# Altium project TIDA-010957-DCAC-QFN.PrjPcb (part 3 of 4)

## Sheet TIDA-010957-DCAC-Current-Sensing.SchDoc
size 431 x 279 mm; Date: Not shown in title block; ApprovedBy: Not shown in title block; CheckedBy: Not shown in title block; Author: Not shown in title block; CompanyName: Not shown in title block; Engineer: Not shown in title block; Organization: Not shown in title block; Address1: Not shown in title block; Address2: Not shown in title block; Address3: Not shown in title block; Address4: Not shown in title block; DocumentNumber: 1; Revision: Use project parameter SCH_Rev; SheetNumber: 6; SheetTotal: 12; PageSetup: Record=PageOptions¦CenterHorizontal=True¦CenterVertical=True¦PrintScale=1.00¦XCorrection=1.00¦YCorrection=1.00¦PrintKind=0¦BorderSize=5000000¦LeftOffset=0¦BottomOffset=0¦Orientation=2¦PaperLength=1000¦PaperWidth=1000¦Scale=100¦PaperSource=15¦PrintQuality=600¦MediaType=1¦DitherType=10¦PaperKind=Letter¦PrintScaleMode=1
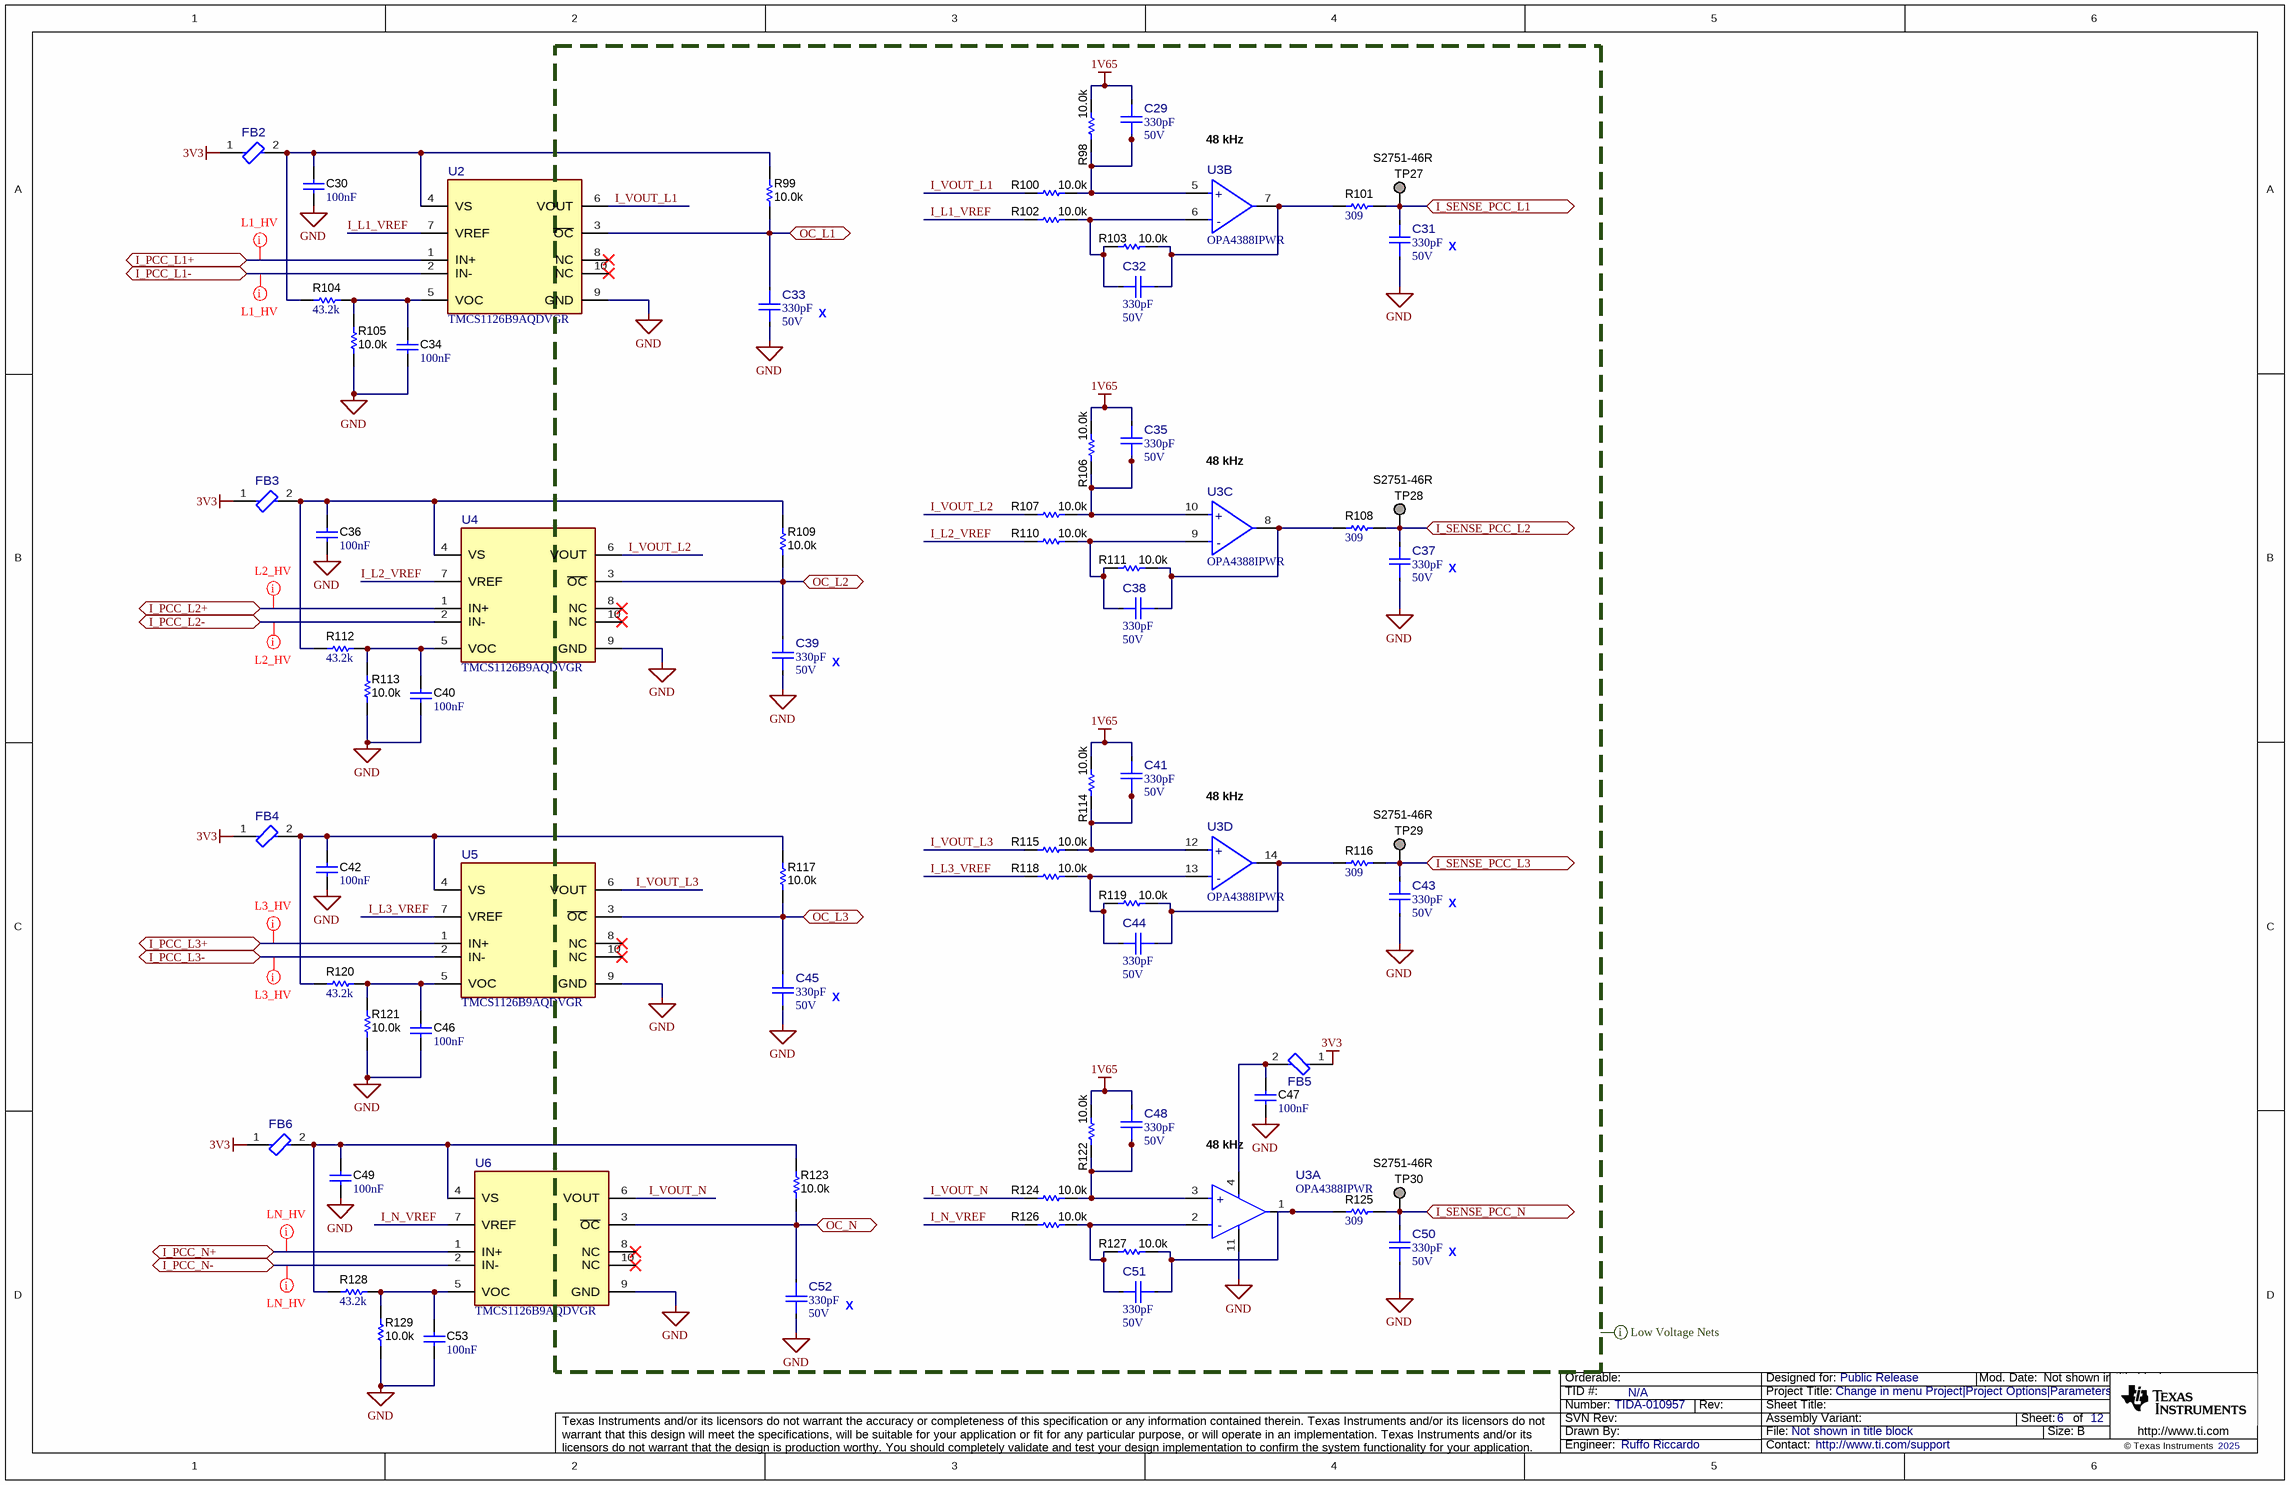
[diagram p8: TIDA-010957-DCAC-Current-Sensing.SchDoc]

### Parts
C29  ValueDisplayed: 330pF  VDC_V: 50V  [FP-CGA3E2C0G1H331J080AA_0603-MFG]  (hidden comment: CGA3E2C0G1H331J080AA)
C30  Cap_F: 100nF  [0603]  (hidden comment: 06033C104JAT2A)
C31  ValueDisplayed: 330pF  VDC_V: 50V  [FP-CGA3E2C0G1H331J080AA_0603-MFG]  (hidden comment: CGA3E2C0G1H331J080AA)
C32  ValueDisplayed: 330pF  VDC_V: 50V  [FP-CGA3E2C0G1H331J080AA_0603-MFG]  (hidden comment: CGA3E2C0G1H331J080AA)
C33  ValueDisplayed: 330pF  VDC_V: 50V  [FP-CGA3E2C0G1H331J080AA_0603-MFG]  (hidden comment: CGA3E2C0G1H331J080AA)
C34  Cap_F: 100nF  [0603]  (hidden comment: 06033C104JAT2A)
C35  ValueDisplayed: 330pF  VDC_V: 50V  [FP-CGA3E2C0G1H331J080AA_0603-MFG]  (hidden comment: CGA3E2C0G1H331J080AA)
C36  Cap_F: 100nF  [0603]  (hidden comment: 06033C104JAT2A)
C37  ValueDisplayed: 330pF  VDC_V: 50V  [FP-CGA3E2C0G1H331J080AA_0603-MFG]  (hidden comment: CGA3E2C0G1H331J080AA)
C38  ValueDisplayed: 330pF  VDC_V: 50V  [FP-CGA3E2C0G1H331J080AA_0603-MFG]  (hidden comment: CGA3E2C0G1H331J080AA)
C39  ValueDisplayed: 330pF  VDC_V: 50V  [FP-CGA3E2C0G1H331J080AA_0603-MFG]  (hidden comment: CGA3E2C0G1H331J080AA)
C40  Cap_F: 100nF  [0603]  (hidden comment: 06033C104JAT2A)
C41  ValueDisplayed: 330pF  VDC_V: 50V  [FP-CGA3E2C0G1H331J080AA_0603-MFG]  (hidden comment: CGA3E2C0G1H331J080AA)
C42  Cap_F: 100nF  [0603]  (hidden comment: 06033C104JAT2A)
C43  ValueDisplayed: 330pF  VDC_V: 50V  [FP-CGA3E2C0G1H331J080AA_0603-MFG]  (hidden comment: CGA3E2C0G1H331J080AA)
C44  ValueDisplayed: 330pF  VDC_V: 50V  [FP-CGA3E2C0G1H331J080AA_0603-MFG]  (hidden comment: CGA3E2C0G1H331J080AA)
C45  ValueDisplayed: 330pF  VDC_V: 50V  [FP-CGA3E2C0G1H331J080AA_0603-MFG]  (hidden comment: CGA3E2C0G1H331J080AA)
C46  Cap_F: 100nF  [0603]  (hidden comment: 06033C104JAT2A)
C47  Cap_F: 100nF  [0603]  (hidden comment: 06033C104JAT2A)
C48  ValueDisplayed: 330pF  VDC_V: 50V  [FP-CGA3E2C0G1H331J080AA_0603-MFG]  (hidden comment: CGA3E2C0G1H331J080AA)
C49  Cap_F: 100nF  [0603]  (hidden comment: 06033C104JAT2A)
C50  ValueDisplayed: 330pF  VDC_V: 50V  [FP-CGA3E2C0G1H331J080AA_0603-MFG]  (hidden comment: CGA3E2C0G1H331J080AA)
C51  ValueDisplayed: 330pF  VDC_V: 50V  [FP-CGA3E2C0G1H331J080AA_0603-MFG]  (hidden comment: CGA3E2C0G1H331J080AA)
C52  ValueDisplayed: 330pF  VDC_V: 50V  [FP-CGA3E2C0G1H331J080AA_0603-MFG]  (hidden comment: CGA3E2C0G1H331J080AA)
C53  Cap_F: 100nF  [0603]  (hidden comment: 06033C104JAT2A)
FB2  MH1608-601Y  [FP-MH1608-601Y_0603-MFG]  (value not drawn)
FB3  MH1608-601Y  [FP-MH1608-601Y_0603-MFG]  (value not drawn)
FB4  MH1608-601Y  [FP-MH1608-601Y_0603-MFG]  (value not drawn)
FB5  MH1608-601Y  [FP-MH1608-601Y_0603-MFG]  (value not drawn)
FB6  MH1608-601Y  [FP-MH1608-601Y_0603-MFG]  (value not drawn)
R98  ValueDisplayed: 10.0k  [0402L]  (hidden comment: MCS0402MD1002BE100)
R99  ValueDisplayed: 10.0k  [0603]  (hidden comment: CRCW060310K0FKEA)
R100  ValueDisplayed: 10.0k  [0402L]  (hidden comment: MCS0402MD1002BE100)
R101  ValueDisplayed: 309  [0402L]  (hidden comment: CRCW0402309RFKED)
R102  ValueDisplayed: 10.0k  [0402L]  (hidden comment: MCS0402MD1002BE100)
R103  ValueDisplayed: 10.0k  [0402L]  (hidden comment: MCS0402MD1002BE100)
R104  ValueDisplayed: 43.2k  [0603]  (hidden comment: RC0603FR-0743K2L)
R105  ValueDisplayed: 10.0k  [0603]  (hidden comment: CRCW060310K0FKEA)
R106  ValueDisplayed: 10.0k  [0402L]  (hidden comment: MCS0402MD1002BE100)
R107  ValueDisplayed: 10.0k  [0402L]  (hidden comment: MCS0402MD1002BE100)
R108  ValueDisplayed: 309  [0402L]  (hidden comment: CRCW0402309RFKED)
R109  ValueDisplayed: 10.0k  [0603]  (hidden comment: CRCW060310K0FKEA)
R110  ValueDisplayed: 10.0k  [0402L]  (hidden comment: MCS0402MD1002BE100)
R111  ValueDisplayed: 10.0k  [0402L]  (hidden comment: MCS0402MD1002BE100)
R112  ValueDisplayed: 43.2k  [0603]  (hidden comment: RC0603FR-0743K2L)
R113  ValueDisplayed: 10.0k  [0603]  (hidden comment: CRCW060310K0FKEA)
R114  ValueDisplayed: 10.0k  [0402L]  (hidden comment: MCS0402MD1002BE100)
R115  ValueDisplayed: 10.0k  [0402L]  (hidden comment: MCS0402MD1002BE100)
R116  ValueDisplayed: 309  [0402L]  (hidden comment: CRCW0402309RFKED)
R117  ValueDisplayed: 10.0k  [0603]  (hidden comment: CRCW060310K0FKEA)
R118  ValueDisplayed: 10.0k  [0402L]  (hidden comment: MCS0402MD1002BE100)
R119  ValueDisplayed: 10.0k  [0402L]  (hidden comment: MCS0402MD1002BE100)
R120  ValueDisplayed: 43.2k  [0603]  (hidden comment: RC0603FR-0743K2L)
R121  ValueDisplayed: 10.0k  [0603]  (hidden comment: CRCW060310K0FKEA)
R122  ValueDisplayed: 10.0k  [0402L]  (hidden comment: MCS0402MD1002BE100)
R123  ValueDisplayed: 10.0k  [0603]  (hidden comment: CRCW060310K0FKEA)
R124  ValueDisplayed: 10.0k  [0402L]  (hidden comment: MCS0402MD1002BE100)
R125  ValueDisplayed: 309  [0402L]  (hidden comment: CRCW0402309RFKED)
R126  ValueDisplayed: 10.0k  [0402L]  (hidden comment: MCS0402MD1002BE100)
R127  ValueDisplayed: 10.0k  [0402L]  (hidden comment: MCS0402MD1002BE100)
R128  ValueDisplayed: 43.2k  [0603]  (hidden comment: RC0603FR-0743K2L)
R129  ValueDisplayed: 10.0k  [0603]  (hidden comment: CRCW060310K0FKEA)
TP27  S2751-46R  [Harwin_S2751-46R]  (no BOM)
TP28  S2751-46R  [Harwin_S2751-46R]  (no BOM)
TP29  S2751-46R  [Harwin_S2751-46R]  (no BOM)
TP30  S2751-46R  [Harwin_S2751-46R]  (no BOM)
U2  TMCS1126B9AQDVGR  [DVG0010A-MFG]
U3  OPA4388IPWR  [PW0014A-MFG]  (parts A,B,C,D of 4)
U4  TMCS1126B9AQDVGR  [DVG0010A-MFG]
U5  TMCS1126B9AQDVGR  [DVG0010A-MFG]
U6  TMCS1126B9AQDVGR  [DVG0010A-MFG]

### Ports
I_PCC_L1+ (bidir), I_PCC_L1- (bidir), I_PCC_L2+ (bidir), I_PCC_L2- (bidir), I_PCC_L3+ (bidir), I_PCC_L3- (bidir), I_PCC_N+ (bidir), I_PCC_N- (bidir), I_SENSE_PCC_L1 (bidir), I_SENSE_PCC_L2 (bidir), I_SENSE_PCC_L3 (bidir), I_SENSE_PCC_N (bidir), OC_L1 (bidir), OC_L2 (bidir), OC_L3 (bidir), OC_N (bidir)

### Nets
1V65: C29.2 C35.2 C41.2 C48.2 R98.2 R106.2 R114.2 R122.2
3V3: FB2.1 FB3.1 FB4.1 FB5.1 FB6.1
GND: C30.2 C31.1 C33.2 C34.2 C36.2 C37.1 C39.2 C40.2 C42.2 C43.1 C45.2 C46.2 C47.1 C49.2 C50.1 C52.2 C53.2 R105.1 R113.1 R121.1 R129.1 U2.9(GND) U3.11(V-) U4.9(GND) U5.9(GND) U6.9(GND)
I_L1_VREF: R102.2 U2.7(VREF)
I_L2_VREF: R110.2 U4.7(VREF)
I_L3_VREF: R118.2 U5.7(VREF)
I_N_VREF: R126.2 U6.7(VREF)
I_PCC_L1+: U2.1(IN+) ; port I_PCC_L1+
I_PCC_L1-: U2.2(IN-) ; port I_PCC_L1-
I_PCC_L2+: U4.1(IN+) ; port I_PCC_L2+
I_PCC_L2-: U4.2(IN-) ; port I_PCC_L2-
I_PCC_L3+: U5.1(IN+) ; port I_PCC_L3+
I_PCC_L3-: U5.2(IN-) ; port I_PCC_L3-
I_PCC_N+: U6.1(IN+) ; port I_PCC_N+
I_PCC_N-: U6.2(IN-) ; port I_PCC_N-
I_SENSE_PCC_L1: C31.2 R101.2 TP27.1 ; port I_SENSE_PCC_L1
I_SENSE_PCC_L2: C37.2 R108.2 TP28.1 ; port I_SENSE_PCC_L2
I_SENSE_PCC_L3: C43.2 R116.2 TP29.1 ; port I_SENSE_PCC_L3
I_SENSE_PCC_N: C50.2 R125.2 TP30.1 ; port I_SENSE_PCC_N
I_VOUT_L1: R100.2 U2.6(VOUT)
I_VOUT_L2: R107.2 U4.6(VOUT)
I_VOUT_L3: R115.2 U5.6(VOUT)
I_VOUT_N: R124.2 U6.6(VOUT)
OC_L1: C33.1 R99.1 U2.3(~{OC}) ; port OC_L1
OC_L2: C39.1 R109.1 U4.3(~{OC}) ; port OC_L2
OC_L3: C45.1 R117.1 U5.3(~{OC}) ; port OC_L3
OC_N: C52.1 R123.1 U6.3(~{OC}) ; port OC_N
NetC29_1: C29.1 R98.1 R100.1 U3.5(+IN_B)
NetC30_1: C30.1 FB2.2 R99.2 R104.2 U2.4(VS)
NetC32_1: C32.1 R101.1 R103.1 U3.7(OUT_B)
NetC32_2: C32.2 R102.1 R103.2 U3.6(-IN_B)
NetC34_1: C34.1 R104.1 R105.2 U2.5(VOC)
NetC35_1: C35.1 R106.1 R107.1 U3.10(+IN_C)
NetC36_1: C36.1 FB3.2 R109.2 R112.2 U4.4(VS)
NetC38_1: C38.1 R108.1 R111.1 U3.8(OUT_C)
NetC38_2: C38.2 R110.1 R111.2 U3.9(-IN_C)
NetC40_1: C40.1 R112.1 R113.2 U4.5(VOC)
NetC41_1: C41.1 R114.1 R115.1 U3.12(+IN_D)
NetC42_1: C42.1 FB4.2 R117.2 R120.2 U5.4(VS)
NetC44_1: C44.1 R116.1 R119.1 U3.14(OUT_D)
NetC44_2: C44.2 R118.1 R119.2 U3.13(-IN_D)
NetC46_1: C46.1 R120.1 R121.2 U5.5(VOC)
NetC47_2: C47.2 FB5.2 U3.4(V+)
NetC48_1: C48.1 R122.1 R124.1 U3.3(+IN_A)
NetC49_1: C49.1 FB6.2 R123.2 R128.2 U6.4(VS)
NetC51_1: C51.1 R125.1 R127.1 U3.1(OUT_A)
NetC51_2: C51.2 R126.1 R127.2 U3.2(-IN_A)
NetC53_1: C53.1 R128.1 R129.2 U6.5(VOC)

Not connected (* = marked no-connect by the designer): U2 8(NC)* 10(NC)*; U4 8(NC)* 10(NC)*; U5 8(NC)* 10(NC)*; U6 8(NC)* 10(NC)*

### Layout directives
net class LV_NET: 1V65, 3V3, GND, I_L1_VREF, I_L2_VREF, I_L3_VREF, I_N_VREF, I_VOUT_L1, I_VOUT_L2, I_VOUT_L3, I_VOUT_N
net class LN_HV: I_PCC_N+, I_PCC_N-
net class L3_HV: I_PCC_L3+, I_PCC_L3-
net class L1_HV: I_PCC_L1+, I_PCC_L1-
net class L2_HV: I_PCC_L2+, I_PCC_L2-

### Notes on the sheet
- (near U3) 48 kHz
- X
- (near C33) X
- (near C39) X
- (near C45) X
- 48 kHz
- (near C52) X

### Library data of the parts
C29 C31-C33 C35 C37-C39 C41 C43-C45 C48 C50-C52 = CMP-0095085-1: Cap Ceramic 330pF 50V C0G 5% Pad SMD 0603 +125°C Automotive T/R; Manufacturer: TDK; AEC Qualified: Yes; TempCo: 30ppm/°C; Tolerance_%: 0.05%; AEC Grade: Grade 1; SizeZ_mm: 1.1mm
C30 C34 C36 C40 C42 C46 C47 C49 C53 = CMP-0006752-5: CAP, CERM, 0.1 uF, 25 V, +/- 5%, X7R, 0603; Manufacturer: AVX; TaMin_C: -55°C; ESR_ohm: 0.05; Polarized: N; SizeAreaWB_mm2: 4.68; Value1: 0.05 ohm; U/M: EA; Value: 0.1uF; TaMax_C: 125°C; SizeZ_mm: 1; SizeX_mm: 1.6; SizeY_mm: 0.8; Value2: 25V; SizeArea_mm2: 1.28; AEC Category: Q200
FB2-FB6 = CMP-0037505-1: 600 Ohms @ 100 MHz 1 Power, Signal Line Ferrite Bead 0603 (1608 Metric) 1A 200mOhm; Manufacturer: Bourns; DCR_ohm: 0.2; SizeZ_mm: 1mm; AEC Qualified: No; Impedance At Frequency: 600Ω @ 100MHz; Test Frequency: 100MHz; Tolerance_%: 25%
R98 R100 R102 R103 R106 R107 R110 R111 R114 R115 R118 R119 R122 R124 R126 R127 = CMP-0077124-1: RES, 10.0 k, 0.1%, 0.1 W, AEC-Q200 Grade 0, 0402; Manufacturer: Vishay/Beyschlag; Value_Code: 10k0; SizeArea_mm2: 0.5; AEC Qualified: Y; AEC Category: Q200; Res_ohm: 10k; Value: 10.0k; SizeZ_mm: 0.6; EIA_Code: E192; TempCo: 25 ppm/C; AEC Grade: 0; Power_W: 100mW; VDC_V: 50V; Value2: 0.1W; U/M: EA; SizeX_mm: 1.0
R99 R105 R109 R113 R117 R121 R123 R129 = CMP-0021998-4: RES, 10.0 k, 1%, 0.1 W, AEC-Q200 Grade 0, 0603; Manufacturer: Vishay-Dale; Power_W: 100mW; TempCo: 100 ppm/C; Value_Code: 10k0; Value: 10.0k; EIA_Code: E96; Res_ohm: 10k; SizeX_mm: 1.6; SizeY_mm: 0.8; SizeZ_mm: 1; Value2: 0.1W; SizeArea_mm2: 1.28; AEC Qualified: Y; VDC_V: 75V; AEC Category: Q200; AEC Grade: 0
R101 R108 R116 R125 = CMP-0026283-2: RES, 309, 1%, 0.063 W, AEC-Q200 Grade 0, 0402; Manufacturer: Vishay-Dale; Power_W: 63mW; TempCo: 100 ppm/C; Value_Code: 309R; Value: 309; EIA_Code: E96; SizeX_mm: 1; SizeY_mm: 0.5; SizeZ_mm: 0.6; Value2: 0.063W; AEC Qualified: Y; VDC_V: 50V; AEC Category: Q200; AEC Grade: 0
R104 R112 R120 R128 = CMP-0023112-5: RES, 43.2 k, 1%, 0.1 W, 0603; Manufacturer: Yageo; Power_W: 100mW; TempCo: 100 ppm/C; Value_Code: 43k2; Value: 43.2k; EIA_Code: E96; SizeX_mm: 1.6; SizeY_mm: 0.8; SizeZ_mm: 1; Value2: 0.1W; SizeArea_mm2: 1.28; AEC Qualified: N; VDC_V: 75V; AEC Category: Q200; SizeAreaWB_mm2: 4.68
TP27-TP30 = CMP-0003968-1: Test Point, SMT; Manufacturer: Harwin
U2 U4-U6 = CMP-0127485-1: 80ARMS 500kHz Hall-effect current sensor with AFR, reference and ALERT 10-SOIC -40 to 125; Manufacturer: Texas Instruments; SizeZ_mm: 2.65mm; Coil Resistance: 0.7mΩ; Current Sensitivity: 33mV/A; Max Sensing Current: 98.5A; Max Supply Voltage: 5.5V; Min Supply Voltage: 3V; Operating Supply Current: 11mA; Sensing Method: Hall Effect; Sensor Output: Analog Voltage; Standoff Height: 0.1mm; TaMax_C: +125°C; TaMin_C: -40°C; TJmax_C: +165°C
U3 = CMP-0121217-1: Zero-Drift Amplifier 4 Circuit Rail-to-Rail 14-TSSOP; Manufacturer: Texas Instruments; SizeZ_mm: 1.2mm; AEC Qualified: No; Gain Bandwidth: 10MHz; Input Bias Current: 0.00003uA; Input Offset Voltage: 0.00225mV; Max Dual Supply Voltage: 2.75V; Max Supply Voltage: 5.5V; Min Dual Supply Voltage: 1.25V; Min Supply Voltage: 2.5V; Nominal Supply Current: 1.7-1.9mA; Number Of Channels: 4; Output Current Per Channel: 60mA; Response Time: 0.75us; Standoff Height: 0.05mm; TaMax_C: +150°C; TaMin_C: -55°C; Voltage Gain: 126dB

## Sheet TIDA-010957-DCAC-Measurements-Voltages-AC.SchDoc
size 431 x 279 mm; Date: Not shown in title block; ApprovedBy: Not shown in title block; CheckedBy: Not shown in title block; Author: Not shown in title block; CompanyName: Not shown in title block; Engineer: Not shown in title block; Organization: Not shown in title block; Address1: Not shown in title block; Address2: Not shown in title block; Address3: Not shown in title block; Address4: Not shown in title block; DocumentNumber: 1; Revision: Use project parameter SCH_Rev; SheetNumber: 7; SheetTotal: 12; PageSetup: Record=PageOptions¦CenterHorizontal=True¦CenterVertical=True¦PrintScale=1.00¦XCorrection=1.00¦YCorrection=1.00¦PrintKind=0¦BorderSize=5000000¦LeftOffset=0¦BottomOffset=0¦Orientation=2¦PaperLength=1000¦PaperWidth=1000¦Scale=100¦PaperSource=15¦PrintQuality=600¦MediaType=1¦DitherType=10¦PaperKind=Letter¦PrintScaleMode=1
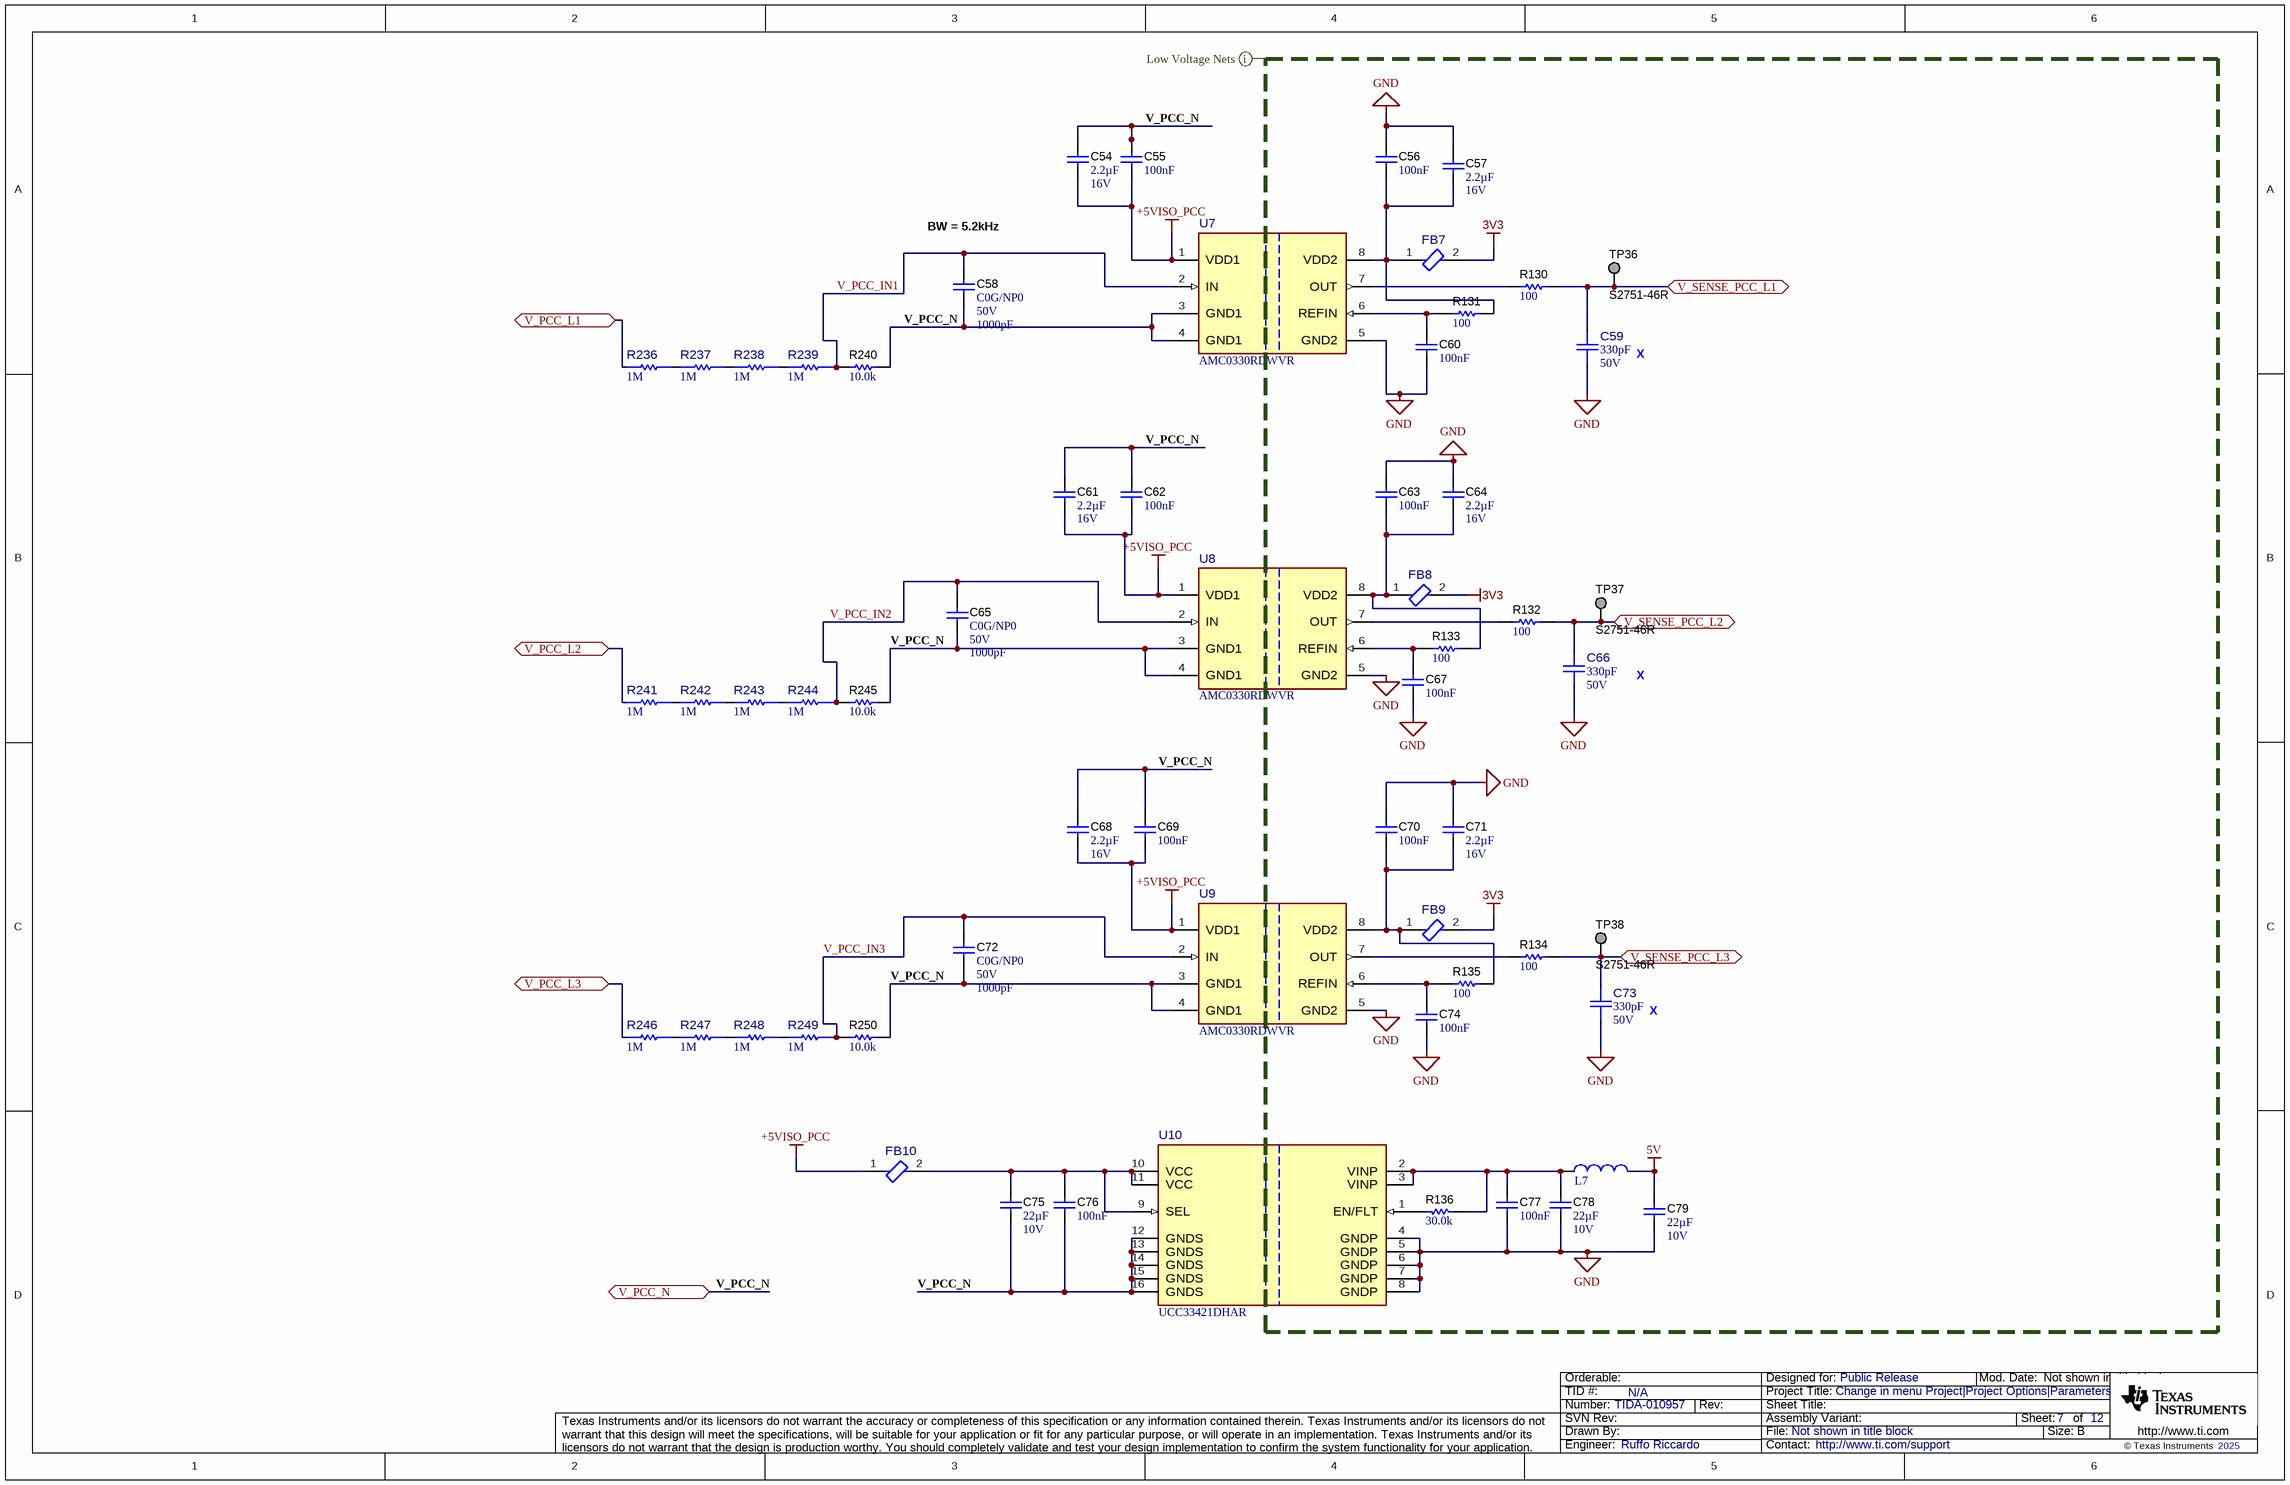
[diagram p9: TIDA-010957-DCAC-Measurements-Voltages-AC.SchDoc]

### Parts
C54  Cap_F: 2.2µF  VDC_V: 16V  [0603]  (hidden comment: EMK107BB7225KA-T)
C55  Cap_F: 100nF  [0603]  (hidden comment: 06033C104JAT2A)
C56  Cap_F: 100nF  [0603]  (hidden comment: 06033C104JAT2A)
C57  Cap_F: 2.2µF  VDC_V: 16V  [0603]  (hidden comment: EMK107BB7225KA-T)
C58  TempCo: C0G/NP0  VDC_V: 50V  ValueDisplayed: 1000pF  [0402L]  (hidden comment: CGA2B2C0G1H102J050BA)
C59  ValueDisplayed: 330pF  VDC_V: 50V  [FP-CGA3E2C0G1H331J080AA_0603-MFG]  (hidden comment: CGA3E2C0G1H331J080AA)
C60  Cap_F: 100nF  [0603]  (hidden comment: 06033C104JAT2A)
C61  Cap_F: 2.2µF  VDC_V: 16V  [0603]  (hidden comment: EMK107BB7225KA-T)
C62  Cap_F: 100nF  [0603]  (hidden comment: 06033C104JAT2A)
C63  Cap_F: 100nF  [0603]  (hidden comment: 06033C104JAT2A)
C64  Cap_F: 2.2µF  VDC_V: 16V  [0603]  (hidden comment: EMK107BB7225KA-T)
C65  TempCo: C0G/NP0  VDC_V: 50V  ValueDisplayed: 1000pF  [0402L]  (hidden comment: CGA2B2C0G1H102J050BA)
C66  ValueDisplayed: 330pF  VDC_V: 50V  [FP-CGA3E2C0G1H331J080AA_0603-MFG]  (hidden comment: CGA3E2C0G1H331J080AA)
C67  Cap_F: 100nF  [0603]  (hidden comment: 06033C104JAT2A)
C68  Cap_F: 2.2µF  VDC_V: 16V  [0603]  (hidden comment: EMK107BB7225KA-T)
C69  Cap_F: 100nF  [0603]  (hidden comment: 06033C104JAT2A)
C70  Cap_F: 100nF  [0603]  (hidden comment: 06033C104JAT2A)
C71  Cap_F: 2.2µF  VDC_V: 16V  [0603]  (hidden comment: EMK107BB7225KA-T)
C72  TempCo: C0G/NP0  VDC_V: 50V  ValueDisplayed: 1000pF  [0402L]  (hidden comment: CGA2B2C0G1H102J050BA)
C73  ValueDisplayed: 330pF  VDC_V: 50V  [FP-CGA3E2C0G1H331J080AA_0603-MFG]  (hidden comment: CGA3E2C0G1H331J080AA)
C74  Cap_F: 100nF  [0603]  (hidden comment: 06033C104JAT2A)
C75  Cap_F: 22µF  VDC_V: 10V  [0805_HV]  (hidden comment: GRM21BZ71A226ME15L)
C76  Cap_F: 100nF  [0603]  (hidden comment: 06033C104JAT2A)
C77  Cap_F: 100nF  [0603]  (hidden comment: 06033C104JAT2A)
C78  Cap_F: 22µF  VDC_V: 10V  [0805_HV]  (hidden comment: GRM21BZ71A226ME15L)
C79  Cap_F: 22µF  VDC_V: 10V  [0805_HV]  (hidden comment: GRM21BZ71A226ME15L)
FB7  MH1608-601Y  [FP-MH1608-601Y_0603-MFG]  (value not drawn)
FB8  MH1608-601Y  [FP-MH1608-601Y_0603-MFG]  (value not drawn)
FB9  MH1608-601Y  [FP-MH1608-601Y_0603-MFG]  (value not drawn)
FB10  MH1608-601Y  [FP-MH1608-601Y_0603-MFG]  (value not drawn)
L7  74479763222  [WE-PMI_0603_L1.6W0.8H0.8]  (value not drawn)
R130  ValueDisplayed: 100  [0402L]  (hidden comment: ERJ-2RKF1000X)
R131  ValueDisplayed: 100  [0402L]  (hidden comment: ERJ-2RKF1000X)
R132  ValueDisplayed: 100  [0402L]  (hidden comment: ERJ-2RKF1000X)
R133  ValueDisplayed: 100  [0402L]  (hidden comment: ERJ-2RKF1000X)
R134  ValueDisplayed: 100  [0402L]  (hidden comment: ERJ-2RKF1000X)
R135  ValueDisplayed: 100  [0402L]  (hidden comment: ERJ-2RKF1000X)
R136  ValueDisplayed: 30.0k  [0402L]  (hidden comment: CRCW040230K0FKED)
R236  Res_ohm: 1M  [FP-RGV3216P-1004-B-T1_1206-MFG]  (hidden comment: RGV3216P-1004-B-T1)
R237  Res_ohm: 1M  [FP-RGV3216P-1004-B-T1_1206-MFG]  (hidden comment: RGV3216P-1004-B-T1)
R238  Res_ohm: 1M  [FP-RGV3216P-1004-B-T1_1206-MFG]  (hidden comment: RGV3216P-1004-B-T1)
R239  Res_ohm: 1M  [FP-RGV3216P-1004-B-T1_1206-MFG]  (hidden comment: RGV3216P-1004-B-T1)
R240  ValueDisplayed: 10.0k  [0603]  (hidden comment: RG1608P-103-B-T5)
R241  Res_ohm: 1M  [FP-RGV3216P-1004-B-T1_1206-MFG]  (hidden comment: RGV3216P-1004-B-T1)
R242  Res_ohm: 1M  [FP-RGV3216P-1004-B-T1_1206-MFG]  (hidden comment: RGV3216P-1004-B-T1)
R243  Res_ohm: 1M  [FP-RGV3216P-1004-B-T1_1206-MFG]  (hidden comment: RGV3216P-1004-B-T1)
R244  Res_ohm: 1M  [FP-RGV3216P-1004-B-T1_1206-MFG]  (hidden comment: RGV3216P-1004-B-T1)
R245  ValueDisplayed: 10.0k  [0603]  (hidden comment: RG1608P-103-B-T5)
R246  Res_ohm: 1M  [FP-RGV3216P-1004-B-T1_1206-MFG]  (hidden comment: RGV3216P-1004-B-T1)
R247  Res_ohm: 1M  [FP-RGV3216P-1004-B-T1_1206-MFG]  (hidden comment: RGV3216P-1004-B-T1)
R248  Res_ohm: 1M  [FP-RGV3216P-1004-B-T1_1206-MFG]  (hidden comment: RGV3216P-1004-B-T1)
R249  Res_ohm: 1M  [FP-RGV3216P-1004-B-T1_1206-MFG]  (hidden comment: RGV3216P-1004-B-T1)
R250  ValueDisplayed: 10.0k  [0603]  (hidden comment: RG1608P-103-B-T5)
TP36  S2751-46R  [Harwin_S2751-46R]  (no BOM)
TP37  S2751-46R  [Harwin_S2751-46R]  (no BOM)
TP38  S2751-46R  [Harwin_S2751-46R]  (no BOM)
U7  AMC0330RDWVR  [DWV0008A-MFG]
U8  AMC0330RDWVR  [DWV0008A-MFG]
U9  AMC0330RDWVR  [DWV0008A-MFG]
U10  UCC33421DHAR  [DHA0016A-MFG]

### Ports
V_PCC_L1 (bidir), V_PCC_L2 (bidir), V_PCC_L3 (bidir), V_PCC_N (bidir), V_SENSE_PCC_L1 (bidir), V_SENSE_PCC_L2 (bidir), V_SENSE_PCC_L3 (bidir)

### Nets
3V3: FB7.2 FB8.2 FB9.2
5V: C79.1 L7.2
+5VISO_PCC: C54.1 C55.2 C61.1 C62.2 C68.1 C69.2 FB10.1 U7.1(VDD1) U8.1(VDD1) U9.1(VDD1)
GND: C56.1 C57.2 C59.1 C60.2 C63.1 C64.2 C66.1 C67.2 C70.1 C71.2 C73.1 C74.2 C77.2 C78.2 C79.2 U7.5(GND2) U8.5(GND2) U9.5(GND2) U10.4(GNDP) U10.5(GNDP) U10.6(GNDP) U10.7(GNDP) U10.8(GNDP)
V_PCC_IN1: C58.1 R239.1 R240.1 U7.2(IN)
V_PCC_IN2: C65.1 R244.1 R245.1 U8.2(IN)
V_PCC_IN3: C72.1 R249.1 R250.1 U9.2(IN)
V_PCC_L1: R236.2 ; port V_PCC_L1
V_PCC_L2: R241.2 ; port V_PCC_L2
V_PCC_L3: R246.2 ; port V_PCC_L3
V_PCC_N: C54.2 C55.1 C58.2 C61.2 C62.1 C65.2 C68.2 C69.1 C72.2 C75.2 C76.2 R240.2 R245.2 R250.2 U7.3(GND1) U7.4(GND1) U8.3(GND1) U8.4(GND1) U9.3(GND1) U9.4(GND1) U10.12(GNDS) U10.13(GNDS) U10.14(GNDS) U10.15(GNDS) U10.16(GNDS) ; port V_PCC_N
V_SENSE_PCC_L1: C59.2 R130.2 TP36.1 ; port V_SENSE_PCC_L1
V_SENSE_PCC_L2: C66.2 R132.2 TP37.1 ; port V_SENSE_PCC_L2
V_SENSE_PCC_L3: C73.2 R134.2 TP38.1 ; port V_SENSE_PCC_L3
NetC56_2: C56.2 C57.1 FB7.1 R131.2 U7.8(VDD2)
NetC60_1: C60.1 R131.1 U7.6(REFIN)
NetC63_2: C63.2 C64.1 FB8.1 R133.2 U8.8(VDD2)
NetC67_1: C67.1 R133.1 U8.6(REFIN)
NetC70_2: C70.2 C71.1 FB9.1 R135.2 U9.8(VDD2)
NetC74_1: C74.1 R135.1 U9.6(REFIN)
NetC75_1: C75.1 C76.1 FB10.2 U10.9(SEL) U10.10(VCC) U10.11(VCC)
NetC77_1: C77.1 C78.1 L7.1 R136.1 U10.2(VINP) U10.3(VINP)
NetR130_1: R130.1 U7.7(OUT)
NetR132_1: R132.1 U8.7(OUT)
NetR134_1: R134.1 U9.7(OUT)
NetR136_2: R136.2 U10.1(EN/FLT)
NetR236_1: R236.1 R237.2
NetR237_1: R237.1 R238.2
NetR238_1: R238.1 R239.2
NetR241_1: R241.1 R242.2
NetR242_1: R242.1 R243.2
NetR243_1: R243.1 R244.2
NetR246_1: R246.1 R247.2
NetR247_1: R247.1 R248.2
NetR248_1: R248.1 R249.2

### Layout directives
net class LV_NET: 3V3, 5V, GND

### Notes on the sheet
- (near C58) BW = 5.2kHz
- X

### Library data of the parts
C54 C57 C61 C64 C68 C71 = CMP-0007121-4: CAP, CERM, 2.2 uF, 16 V, +/- 10%, X7R, 0603; Manufacturer: Taiyo Yuden; TaMin_C: -55°C; Polarized: N; SizeAreaWB_mm2: 4.68; Value1: Unknown; U/M: EA; Value: 2.2uF; TaMax_C: 125°C; SizeZ_mm: 1; SizeX_mm: 1.6; SizeY_mm: 0.8; SizeArea_mm2: 1.28; AEC Category: Q200
C55 C56 C60 C62 C63 C67 C69 C70 C74 C76 C77 = CMP-0006752-5: as C30 on sheet TIDA-010957-DCAC-Current-Sensing
C58 C65 C72 = CMP-0006309-2: CAP, CERM, 1000 pF, 50 V, +/- 5%, C0G/NP0, AEC-Q200 Grade 1, 0402; Manufacturer: TDK; TaMin_C: -55°C; Polarized: N; SizeAreaWB_mm2: 3; Value1: Unknown; U/M: EA; Value: 1000pF; TaMax_C: 125°C; SizeZ_mm: 0.6; SizeX_mm: 1; SizeY_mm: 0.5; Cap_Case: 0402; AEC Qualified: Y; Cap_F: 1nF; AEC Category: Q200
C59 C66 C73 = CMP-0095085-1: as C29 on sheet TIDA-010957-DCAC-Current-Sensing
C75 C78 C79 = CMP-0008377-2: CAP, CERM, 22 uF, 10 V, +/- 20%, X7R, 0805; Manufacturer: MuRata; SizeY_mm: 1.25; Cap_Case: 0805; SizeArea_mm2: 2.5; AEC Qualified: N; AEC Category: Q200; ValueDisplayed: 22uF; TaMin_C: -55°C; SizeAreaWB_mm2: 6.75; Value1: Unknown; U/M: EA; Value: 22uF; TaMax_C: 125°C; SizeZ_mm: 1.45; SizeX_mm: 2
FB7-FB10 = CMP-0037505-1: as FB2-FB6 on sheet TIDA-010957-DCAC-Current-Sensing
L7 = CMP-0100992-1: WE-PMI SMT Power Multilayer Inductor, size 0603, 2.2uH, 0.8A, 375mOhm; Manufacturer: Wurth Elektronik; Case/Size Code: 0603; Inductance Tolerance: 20%; Q Factor: 15; Saturation Current: 0.28A; Self Resonant Frequency: 80MHz; Type: Low RDC
R130-R135 = CMP-0026656-1: RES, 100, 1%, 0.1 W, 0402; Manufacturer: Panasonic; Power_W: 100mW; TempCo: 100 ppm/C; Value_Code: 100R; U/M: EA; Value: 100; EIA_Code: E96; SizeX_mm: 1; SizeY_mm: 0.5; SizeZ_mm: 0.6; Value2: 0.1W; VDC_V: 50V; AEC Category: Q200
R136 = CMP-0078244-2: RES, 30.0 k, 1%, 0.063 W, AEC-Q200 Grade 0, 0402; Manufacturer: Vishay-Dale; Power_W: 63mW; Green_Lifecycle: Active; TempCo: 100 ppm/C; Value_Code: 30k0; Green_REACh: Passed; Value: 30.0k; Res_ohm: 30k; SizeX_mm: 1; SizeY_mm: 0.5; SizeZ_mm: 0.6; Value2: 0.063W; AEC Qualified: Y; VDC_V: 50V; AEC Grade: 0; AEC Category: Q200
R236-R239 R241-R244 R246-R249 = CMP-0097198-1: 1 MOhms ±0.1% 0.25W, 1/4W Chip Resistor 1206 (3216 Metric) Anti-Sulfur, Automotive AEC-Q200, High Voltage Thin Film; Manufacturer: Susumu; AEC Qualified: Yes; VDC_V: 700V; Power_W: 250mW; TempCo: 25ppm/°C; AEC Grade: Grade 0; Value: 1M; SizeZ_mm: 0.55mm
R240 R245 R250 = CMP-0023404-3: RES, 10.0 k, 0.1%, 0.1 W, 0603; Manufacturer: Susumu Co Ltd; Power_W: 100mW; TempCo: 25 ppm/C; Value_Code: 10k0; U/M: EA; Value: 10.0k; EIA_Code: E192; Res_ohm: 10k; SizeX_mm: 1.6; SizeY_mm: 0.8; SizeZ_mm: 1; Value2: 0.1W; SizeArea_mm2: 1.28; VDC_V: 75V; AEC Category: Q200
TP36-TP38 = CMP-0003968-1: Test Point, SMT; Manufacturer: Harwin
U7-U9 = CMP-0122725-1: Automotive, Precision, ±1V Input Isolated Amplifiers With Single-Ended, Ratiometric Output; Manufacturer: Texas Instruments; SizeZ_mm: 2.8mm; AEC Qualified: Yes; AEC Grade: Grade 1; Bandwidth: 110kHz; Input Bias Current: 0.0035uA; Input Offset Voltage: 0.4mV; Max Supply Voltage: 5.5V; Min Supply Voltage: 3V; Number Of Channels: 1; Output Current Per Channel: 14mA; Response Time: 500us; Standoff Height: 0.36mm; TaMax_C: +125°C; TaMin_C: -40°C; TJmax_C: +150°C
U10 = CMP-0123146-1: Ultra-Small, 1.5W, 5.0V, 5kVRMS Isolation, Industrial DC/DC Module; Manufacturer: Texas Instruments; SizeZ_mm: 2.6mm; AEC Qualified: No; Max Supply Voltage: 5.5V; Min Supply Voltage: 4.5V; Nominal Supply Current: 7-545mA; Number Of Outputs: 1; Output Type: AdjustableProgrammable; Output Voltage: 5/5.5V; Standoff Height: 0.1mm; Switching Frequency: 76MHz; Switching Topology: Boost; TaMax_C: +125°C; TaMin_C: -40°C; TJmax_C: +150°C

## Sheet TIDA-010957-DCAC-DC-Voltage-Measurements.SchDoc
size 431 x 279 mm; Date: Not shown in title block; ApprovedBy: Not shown in title block; CheckedBy: Not shown in title block; Author: Not shown in title block; CompanyName: Not shown in title block; Engineer: Not shown in title block; Organization: Not shown in title block; Address1: Not shown in title block; Address2: Not shown in title block; Address3: Not shown in title block; Address4: Not shown in title block; DocumentNumber: 1; Revision: Use project parameter SCH_Rev; SheetNumber: 8; SheetTotal: 12; PageSetup: Record=PageOptions¦CenterHorizontal=True¦CenterVertical=True¦PrintScale=1.00¦XCorrection=1.00¦YCorrection=1.00¦PrintKind=0¦BorderSize=5000000¦LeftOffset=0¦BottomOffset=0¦Orientation=2¦PaperLength=1000¦PaperWidth=1000¦Scale=100¦PaperSource=15¦PrintQuality=600¦MediaType=1¦DitherType=10¦PaperKind=Letter¦PrintScaleMode=1
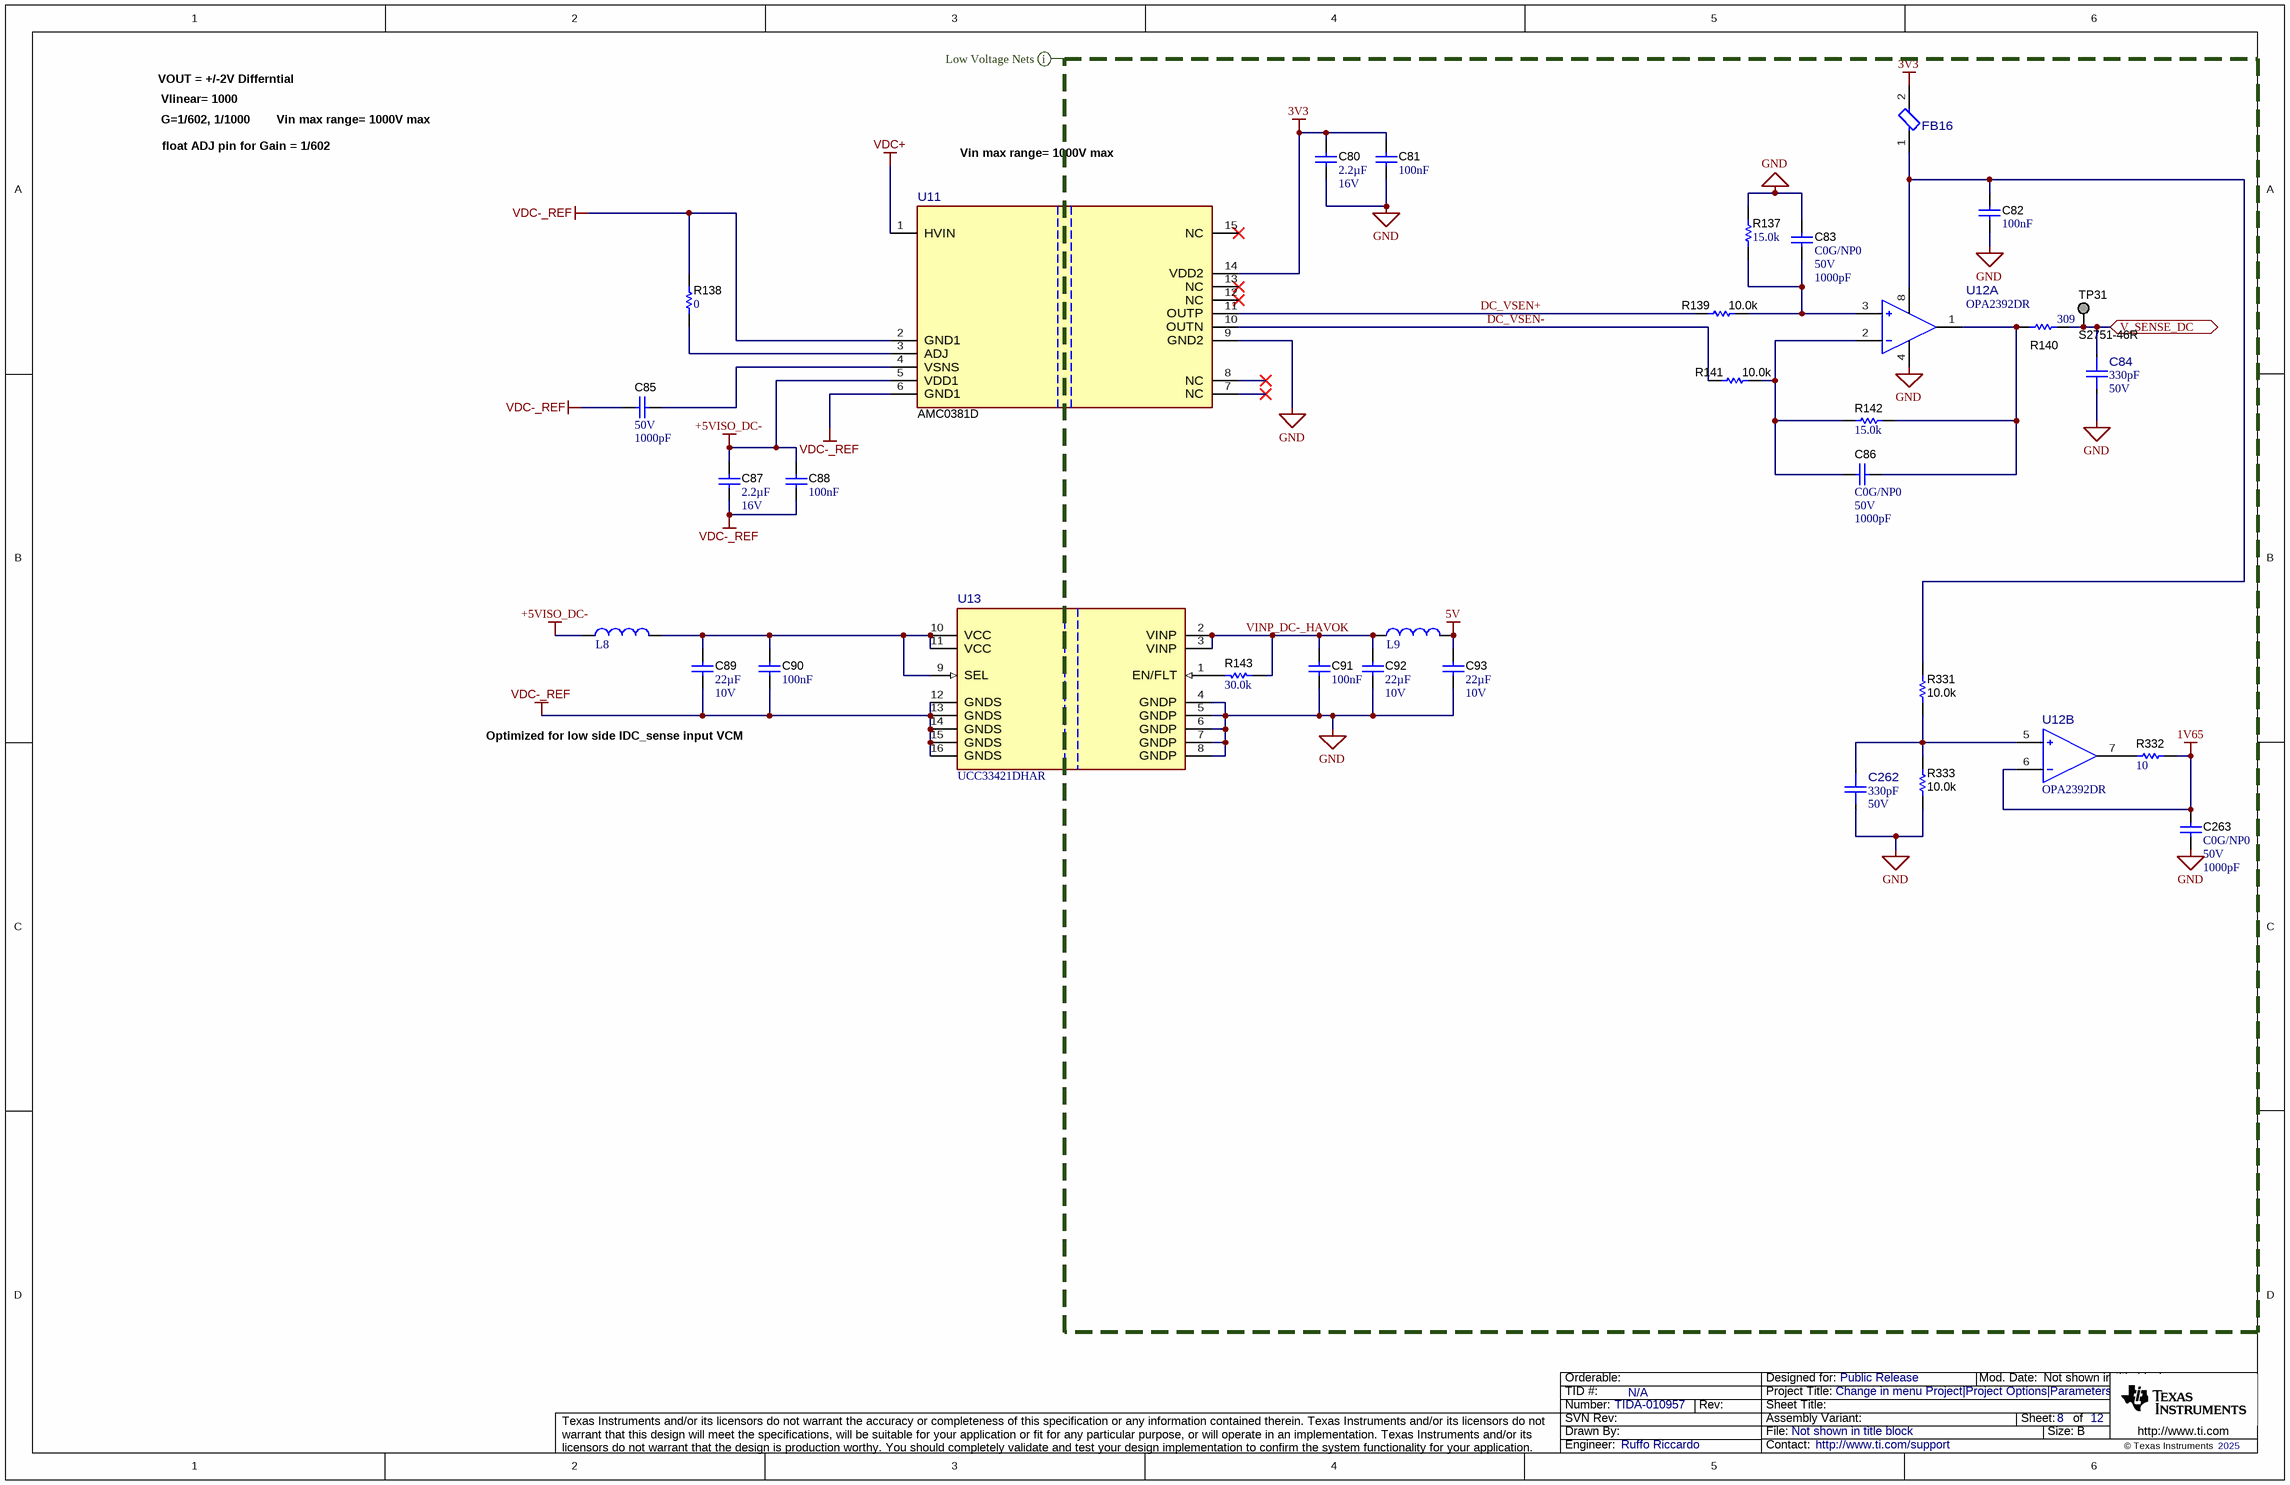
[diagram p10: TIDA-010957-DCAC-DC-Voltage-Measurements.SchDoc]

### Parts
C80  Cap_F: 2.2µF  VDC_V: 16V  [0603]  (hidden comment: EMK107BB7225KA-T)
C81  Cap_F: 100nF  [0603]  (hidden comment: 06033C104JAT2A)
C82  Cap_F: 100nF  [0603]  (hidden comment: 06033C104JAT2A)
C83  TempCo: C0G/NP0  VDC_V: 50V  ValueDisplayed: 1000pF  [0402L]  (hidden comment: CGA2B2C0G1H102J050BA)
C84  ValueDisplayed: 330pF  VDC_V: 50V  [FP-CGA3E2C0G1H331J080AA_0603-MFG]  (hidden comment: CGA3E2C0G1H331J080AA)
C85  VDC_V: 50V  ValueDisplayed: 1000pF  [0402L]  (hidden comment: GRM155R71H102KA01D)
C86  TempCo: C0G/NP0  VDC_V: 50V  ValueDisplayed: 1000pF  [0402L]  (hidden comment: CGA2B2C0G1H102J050BA)
C87  Cap_F: 2.2µF  VDC_V: 16V  [0603]  (hidden comment: EMK107BB7225KA-T)
C88  Cap_F: 100nF  [0603]  (hidden comment: 06033C104JAT2A)
C89  Cap_F: 22µF  VDC_V: 10V  [0805_HV]  (hidden comment: GRM21BZ71A226ME15L)
C90  Cap_F: 100nF  [0603]  (hidden comment: 06033C104JAT2A)
C91  Cap_F: 100nF  [0603]  (hidden comment: 06033C104JAT2A)
C92  Cap_F: 22µF  VDC_V: 10V  [0805_HV]  (hidden comment: GRM21BZ71A226ME15L)
C93  Cap_F: 22µF  VDC_V: 10V  [0805_HV]  (hidden comment: GRM21BZ71A226ME15L)
C262  ValueDisplayed: 330pF  VDC_V: 50V  [FP-CGA3E2C0G1H331J080AA_0603-MFG]  (hidden comment: CGA3E2C0G1H331J080AA)
C263  TempCo: C0G/NP0  VDC_V: 50V  ValueDisplayed: 1000pF  [0402L]  (hidden comment: CGA2B2C0G1H102J050BA)
FB16  MH1608-601Y  [FP-MH1608-601Y_0603-MFG]  (value not drawn)
L8  74479763222  [WE-PMI_0603_L1.6W0.8H0.8]  (value not drawn)
L9  74479763222  [WE-PMI_0603_L1.6W0.8H0.8]  (value not drawn)
R137  ValueDisplayed: 15.0k  [0402L]  (hidden comment: ERA-2AEB153X)
R138  ValueDisplayed: 0  [0402L]  (hidden comment: RC0402JR-070RL)
R139  ValueDisplayed: 10.0k  [0402L]  (hidden comment: MCS0402MD1002BE100)
R140  ValueDisplayed: 309  [0402L]  (hidden comment: CRCW0402309RFKED)
R141  ValueDisplayed: 10.0k  [0402L]  (hidden comment: MCS0402MD1002BE100)
R142  ValueDisplayed: 15.0k  [0402L]  (hidden comment: ERA-2AEB153X)
R143  ValueDisplayed: 30.0k  [0402L]  (hidden comment: CRCW040230K0FKED)
R331  ValueDisplayed: 10.0k  [0402L]  (hidden comment: MCS0402MD1002BE100)
R332  ValueDisplayed: 10  [0402L]  (hidden comment: CRCW040210R0JNED)
R333  ValueDisplayed: 10.0k  [0402L]  (hidden comment: MCS0402MD1002BE100)
TP31  S2751-46R  [Harwin_S2751-46R]  (no BOM)
U11  AMC0381D  [DFX0015A-MFG]
U12  OPA2392DR  [D0008A-MFG]  (parts A,B of 2)
U13  UCC33421DHAR  [DHA0016A-MFG]

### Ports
V_SENSE_DC (bidir)

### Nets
1V65: C263.2 R332.1 U12.6(-IN_B)
3V3: C80.2 C81.1 FB16.2 U11.14(VDD2)
5V: C93.1 L9.2
+5VISO_DC-: C87.2 C88.1 L8.2 U11.5(VDD1)
GND: C80.1 C81.2 C82.2 C83.1 C84.2 C91.2 C92.2 C93.2 C262.2 C263.1 R137.2 R333.2 U11.9(GND2) U12.4(V-) U13.4(GNDP) U13.5(GNDP) U13.6(GNDP) U13.7(GNDP) U13.8(GNDP)
VDC+: U11.1(HVIN)
VDC-_REF: C85.1 C87.1 C88.2 C89.2 C90.2 R138.2 U11.2(GND1) U11.6(GND1) U13.12(GNDS) U13.13(GNDS) U13.14(GNDS) U13.15(GNDS) U13.16(GNDS)  [project net GND_S4_GaN]
DC_VSEN+: R139.2 U11.11(OUTP)
DC_VSEN-: R141.2 U11.10(OUTN)
V_SENSE_DC: C84.1 R140.2 TP31.1 ; port V_SENSE_DC
VINP_DC-_HAVOK: C91.1 C92.1 L9.1 R143.1 U13.2(VINP) U13.3(VINP)
NetC82_1: C82.1 FB16.1 R331.1 U12.8(V+)
NetC83_2: C83.2 R137.1 R139.1 U12.3(+IN_A)
NetC85_2: C85.2 U11.4(VSNS)
NetC86_1: C86.1 R141.1 R142.1 U12.2(-IN_A)
NetC86_2: C86.2 R140.1 R142.2 U12.1(OUT_A)
NetC89_1: C89.1 C90.1 L8.1 U13.9(SEL) U13.10(VCC) U13.11(VCC)
NetC262_1: C262.1 R331.2 R333.1 U12.5(+IN_B)
NetR138_1: R138.1 U11.3(ADJ)
NetR143_2: R143.2 U13.1(EN/FLT)
NetR332_2: R332.2 U12.7(OUT_B)

Not connected (* = marked no-connect by the designer): U11 7(NC)* 8(NC)* 12(NC)* 13(NC)* 15(NC)*

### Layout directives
net class LV_NET: 1V65, 3V3, 5V, DC_VSEN+, DC_VSEN-, GND, VINP_DC-_HAVOK

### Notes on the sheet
- Vlinear= 1000
- VOUT = +/-2V Differntial
- G=1/602, 1/1000
- float ADJ pin for Gain = 1/602
- Vin max range= 1000V max
- Optimized for low side IDC_sense input VCM

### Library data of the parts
C80 C87 = CMP-0007121-4: as C54 on sheet TIDA-010957-DCAC-Measurements-Voltages-AC
C81 C82 C88 C90 C91 = CMP-0006752-5: as C30 on sheet TIDA-010957-DCAC-Current-Sensing
C83 C86 C263 = CMP-0006309-2: as C58 on sheet TIDA-010957-DCAC-Measurements-Voltages-AC
C84 C262 = CMP-0095085-1: as C29 on sheet TIDA-010957-DCAC-Current-Sensing
C85 = CMP-0006673-2: CAP, CERM, 1000 pF, 50 V, +/- 10%, X7R, 0402; Manufacturer: MuRata; TaMin_C: -55°C; Polarized: N; SizeAreaWB_mm2: 3; Value1: Unknown; U/M: EA; Value: 1000pF; TaMax_C: 125°C; SizeZ_mm: 0.6; SizeX_mm: 1; SizeY_mm: 0.5; Cap_Case: 0402; Cap_F: 1nF; AEC Category: Q200
C89 C92 C93 = CMP-0008377-2: as C75 on sheet TIDA-010957-DCAC-Measurements-Voltages-AC
FB16 = CMP-0037505-1: as FB2-FB6 on sheet TIDA-010957-DCAC-Current-Sensing
L8 L9 = CMP-0100992-1: as L7 on sheet TIDA-010957-DCAC-Measurements-Voltages-AC
R137 R142 = CMP-0065359-1: RES, 15.0 k, .1%, .063 W, AEC-Q200 Grade 0, 0402; Manufacturer: Panasonic; Power_W: 63mW; TempCo: 25 ppm/C; Value_Code: 15k0; U/M: EA; Value: 15.0k; EIA_Code: E192; Tolerance_%: 0.1%; Res_ohm: 15k; SizeX_mm: 1.0; SizeY_mm: 0.5; SizeZ_mm: 0.6; Value2: .063W; AEC Qualified: Y; VDC_V: 50V; AEC Grade: 0; AEC Category: Q200
R138 = CMP-0027004-2: RES, 0, 5%, 0.063 W, 0402; Manufacturer: Yageo America; Power_W: 63mW; TempCo: 200 ppm/C; Value_Code: 0000; U/M: EA; Value: 0; EIA_Code: E24; SizeX_mm: 1; SizeY_mm: 0.5; SizeZ_mm: 0.6; Value2: 0.063W; VDC_V: 50V; AEC Category: Q200
R139 R141 R331 R333 = CMP-0077124-1: as R98 on sheet TIDA-010957-DCAC-Current-Sensing
R140 = CMP-0026283-2: as R101 on sheet TIDA-010957-DCAC-Current-Sensing
R143 = CMP-0078244-2: as R136 on sheet TIDA-010957-DCAC-Measurements-Voltages-AC
R332 = CMP-0026827-3: RES, 10, 5%, 0.063 W, AEC-Q200 Grade 0, 0402; Manufacturer: Vishay-Dale; Power_W: 63mW; TempCo: 200 ppm/C; Value_Code: 10R0; Value: 10; EIA_Code: E24; SizeX_mm: 1; SizeY_mm: 0.5; SizeZ_mm: 0.6; Value2: 0.063W; AEC Qualified: Y; VDC_V: 50V; AEC Category: Q200; AEC Grade: 0
TP31 = CMP-0003968-1: Test Point, SMT; Manufacturer: Harwin
U11 = CMP-0044881-2: Manufacturer: Texas Instruments; SizeZ_mm: 3.55mm; Standoff Height: 0.1mm; AEC Category: Q200; CompType: IC
U12 = CMP-0121707-1: Precision, Low-Offset-Voltage, Low-Noise, Low-Input-Bias-Current, Rail-to-Rail I/O, e-trim™ Operational Amplifiers; Manufacturer: Texas Instruments; SizeZ_mm: 1.75mm; AEC Qualified: No; Gain Bandwidth: 13MHz; Input Bias Current: 0.00000001uA; Input Offset Voltage: 0.001mV; Max Dual Supply Voltage: 2.75V; Max Supply Voltage: 5.5V; Min Dual Supply Voltage: 850mV; Min Supply Voltage: 1.7V; Nominal Supply Current: 1.22mA; Number Of Channels: 2; Output Current Per Channel: 65mA; Response Time: 1us; Standoff Height: 0.11mm; TaMax_C: +125°C; TaMin_C: -40°C; TJmax_C: +150°C; Voltage Gain: 132dB
U13 = CMP-0123146-1: as U10 on sheet TIDA-010957-DCAC-Measurements-Voltages-AC

## Sheet TIDA-010957-DCAC-FC-OP-AMP.SchDoc
size 431 x 279 mm; Date: Not shown in title block; ApprovedBy: Not shown in title block; CheckedBy: Not shown in title block; Author: Not shown in title block; CompanyName: Not shown in title block; Engineer: Not shown in title block; Organization: Not shown in title block; Address1: Not shown in title block; Address2: Not shown in title block; Address3: Not shown in title block; Address4: Not shown in title block; DocumentNumber: 1; Revision: Use project parameter SCH_Rev; SheetNumber: 9; SheetTotal: 12; PageSetup: Record=PageOptions¦CenterHorizontal=True¦CenterVertical=True¦PrintScale=1.00¦XCorrection=1.00¦YCorrection=1.00¦PrintKind=0¦BorderSize=5000000¦LeftOffset=0¦BottomOffset=0¦Orientation=2¦PaperLength=1000¦PaperWidth=1000¦Scale=100¦PaperSource=15¦PrintQuality=600¦MediaType=1¦DitherType=10¦PaperKind=Letter¦PrintScaleMode=1
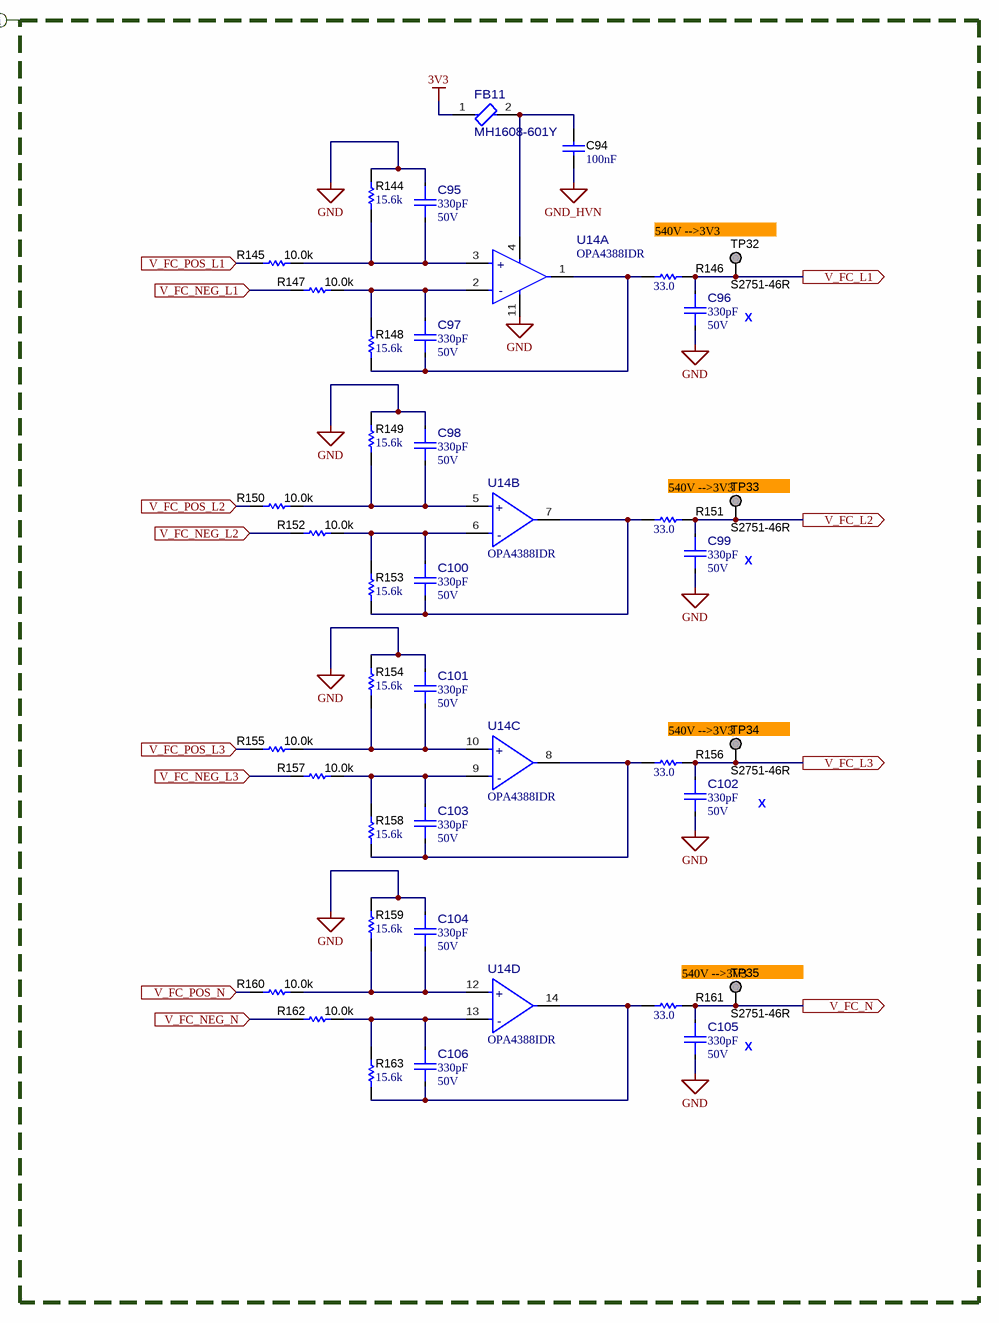
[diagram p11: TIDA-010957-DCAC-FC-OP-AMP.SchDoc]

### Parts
C94  Cap_F: 100nF  [0603]  (hidden comment: 06033C104JAT2A)
C95  ValueDisplayed: 330pF  VDC_V: 50V  [FP-CGA3E2C0G1H331J080AA_0603-MFG]  (hidden comment: CGA3E2C0G1H331J080AA)
C96  ValueDisplayed: 330pF  VDC_V: 50V  [FP-CGA3E2C0G1H331J080AA_0603-MFG]  (hidden comment: CGA3E2C0G1H331J080AA)
C97  ValueDisplayed: 330pF  VDC_V: 50V  [FP-CGA3E2C0G1H331J080AA_0603-MFG]  (hidden comment: CGA3E2C0G1H331J080AA)
C98  ValueDisplayed: 330pF  VDC_V: 50V  [FP-CGA3E2C0G1H331J080AA_0603-MFG]  (hidden comment: CGA3E2C0G1H331J080AA)
C99  ValueDisplayed: 330pF  VDC_V: 50V  [FP-CGA3E2C0G1H331J080AA_0603-MFG]  (hidden comment: CGA3E2C0G1H331J080AA)
C100  ValueDisplayed: 330pF  VDC_V: 50V  [FP-CGA3E2C0G1H331J080AA_0603-MFG]  (hidden comment: CGA3E2C0G1H331J080AA)
C101  ValueDisplayed: 330pF  VDC_V: 50V  [FP-CGA3E2C0G1H331J080AA_0603-MFG]  (hidden comment: CGA3E2C0G1H331J080AA)
C102  ValueDisplayed: 330pF  VDC_V: 50V  [FP-CGA3E2C0G1H331J080AA_0603-MFG]  (hidden comment: CGA3E2C0G1H331J080AA)
C103  ValueDisplayed: 330pF  VDC_V: 50V  [FP-CGA3E2C0G1H331J080AA_0603-MFG]  (hidden comment: CGA3E2C0G1H331J080AA)
C104  ValueDisplayed: 330pF  VDC_V: 50V  [FP-CGA3E2C0G1H331J080AA_0603-MFG]  (hidden comment: CGA3E2C0G1H331J080AA)
C105  ValueDisplayed: 330pF  VDC_V: 50V  [FP-CGA3E2C0G1H331J080AA_0603-MFG]  (hidden comment: CGA3E2C0G1H331J080AA)
C106  ValueDisplayed: 330pF  VDC_V: 50V  [FP-CGA3E2C0G1H331J080AA_0603-MFG]  (hidden comment: CGA3E2C0G1H331J080AA)
FB11  MH1608-601Y  [FP-MH1608-601Y_0603-MFG]
R144  ValueDisplayed: 15.6k  [0603]  (hidden comment: RT0603BRD0715K6L)
R145  ValueDisplayed: 10.0k  [0402L]  (hidden comment: MCS0402MD1002BE100)
R146  ValueDisplayed: 33.0  [0402L]  (hidden comment: ERJ-2RKF33R0X)
R147  ValueDisplayed: 10.0k  [0402L]  (hidden comment: MCS0402MD1002BE100)
R148  ValueDisplayed: 15.6k  [0603]  (hidden comment: RT0603BRD0715K6L)
R149  ValueDisplayed: 15.6k  [0603]  (hidden comment: RT0603BRD0715K6L)
R150  ValueDisplayed: 10.0k  [0402L]  (hidden comment: MCS0402MD1002BE100)
R151  ValueDisplayed: 33.0  [0402L]  (hidden comment: ERJ-2RKF33R0X)
R152  ValueDisplayed: 10.0k  [0402L]  (hidden comment: MCS0402MD1002BE100)
R153  ValueDisplayed: 15.6k  [0603]  (hidden comment: RT0603BRD0715K6L)
R154  ValueDisplayed: 15.6k  [0603]  (hidden comment: RT0603BRD0715K6L)
R155  ValueDisplayed: 10.0k  [0402L]  (hidden comment: MCS0402MD1002BE100)
R156  ValueDisplayed: 33.0  [0402L]  (hidden comment: ERJ-2RKF33R0X)
R157  ValueDisplayed: 10.0k  [0402L]  (hidden comment: MCS0402MD1002BE100)
R158  ValueDisplayed: 15.6k  [0603]  (hidden comment: RT0603BRD0715K6L)
R159  ValueDisplayed: 15.6k  [0603]  (hidden comment: RT0603BRD0715K6L)
R160  ValueDisplayed: 10.0k  [0402L]  (hidden comment: MCS0402MD1002BE100)
R161  ValueDisplayed: 33.0  [0402L]  (hidden comment: ERJ-2RKF33R0X)
R162  ValueDisplayed: 10.0k  [0402L]  (hidden comment: MCS0402MD1002BE100)
R163  ValueDisplayed: 15.6k  [0603]  (hidden comment: RT0603BRD0715K6L)
TP32  S2751-46R  [Harwin_S2751-46R]  (no BOM)
TP33  S2751-46R  [Harwin_S2751-46R]  (no BOM)
TP34  S2751-46R  [Harwin_S2751-46R]  (no BOM)
TP35  S2751-46R  [Harwin_S2751-46R]  (no BOM)
U14  OPA4388IDR  [D0014A-MFG]  (parts A,B,C,D of 4)

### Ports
V_FC_L1 (out), V_FC_L2 (out), V_FC_L3 (out), V_FC_N (out), V_FC_NEG_L1 (in), V_FC_NEG_L2 (in), V_FC_NEG_L3 (in), V_FC_NEG_N (in), V_FC_POS_L1 (in), V_FC_POS_L2 (in), V_FC_POS_L3 (in), V_FC_POS_N (in)

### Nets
3V3: FB11.1
GND: C95.1 C96.2 C98.1 C99.2 C101.1 C102.2 C104.1 C105.2 R144.2 R149.2 R154.2 R159.2 U14.11(V-)
GND_HVN: C94.2
V_FC_L1: C96.1 R146.2 TP32.1 ; port V_FC_L1
V_FC_L2: C99.1 R151.2 TP33.1 ; port V_FC_L2
V_FC_L3: C102.1 R156.2 TP34.1 ; port V_FC_L3
V_FC_N: C105.1 R161.2 TP35.1 ; port V_FC_N
V_FC_NEG_L1: R147.2 ; port V_FC_NEG_L1
V_FC_NEG_L2: R152.2 ; port V_FC_NEG_L2
V_FC_NEG_L3: R157.2 ; port V_FC_NEG_L3
V_FC_NEG_N: R162.2 ; port V_FC_NEG_N
V_FC_POS_L1: R145.2 ; port V_FC_POS_L1
V_FC_POS_L2: R150.2 ; port V_FC_POS_L2
V_FC_POS_L3: R155.2 ; port V_FC_POS_L3
V_FC_POS_N: R160.2 ; port V_FC_POS_N
NetC94_1: C94.1 FB11.2 U14.4(V+)
NetC95_2: C95.2 R144.1 R145.1 U14.3(+IN_A)
NetC97_1: C97.1 R147.1 R148.2 U14.2(-IN_A)
NetC97_2: C97.2 R146.1 R148.1 U14.1(OUT_A)
NetC98_2: C98.2 R149.1 R150.1 U14.5(+IN_B)
NetC100_1: C100.1 R152.1 R153.2 U14.6(-IN_B)
NetC100_2: C100.2 R151.1 R153.1 U14.7(OUT_B)
NetC101_2: C101.2 R154.1 R155.1 U14.10(+IN_C)
NetC103_1: C103.1 R157.1 R158.2 U14.9(-IN_C)
NetC103_2: C103.2 R156.1 R158.1 U14.8(OUT_C)
NetC104_2: C104.2 R159.1 R160.1 U14.12(+IN_D)
NetC106_1: C106.1 R162.1 R163.2 U14.13(-IN_D)
NetC106_2: C106.2 R161.1 R163.1 U14.14(OUT_D)

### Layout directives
net class LV_NET: 3V3, GND, GND_HVN

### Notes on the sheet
- 540V -->3V3
- X
- (near TP33) 540V -->3V3
- (near TP34) 540V -->3V3
- (near TP35) 540V -->3V3

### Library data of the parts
C94 = CMP-0006752-5: as C30 on sheet TIDA-010957-DCAC-Current-Sensing
C95-C106 = CMP-0095085-1: as C29 on sheet TIDA-010957-DCAC-Current-Sensing
FB11 = CMP-0037505-1: as FB2-FB6 on sheet TIDA-010957-DCAC-Current-Sensing
R144 R148 R149 R153 R154 R158 R159 R163 = CMP-0023778-2: RES, 15.6 k, 0.1%, 0.1 W, 0603; Manufacturer: Yageo America; Power_W: 100mW; TempCo: 25 ppm/C; Value_Code: 15k6; U/M: EA; Value: 15.6k; EIA_Code: E192; SizeX_mm: 1.6; SizeY_mm: 0.8; SizeZ_mm: 1; Value2: 0.1W; SizeArea_mm2: 1.28; VDC_V: 75V; AEC Category: Q200
R145 R147 R150 R152 R155 R157 R160 R162 = CMP-0077124-1: as R98 on sheet TIDA-010957-DCAC-Current-Sensing
R146 R151 R156 R161 = CMP-0026696-1: RES, 33.0, 1%, 0.1 W, 0402; Manufacturer: Panasonic; Power_W: 100mW; TempCo: 100 ppm/C; Value_Code: 33R0; U/M: EA; Value: 33.0; Res_ohm: 33; SizeX_mm: 1; SizeY_mm: 0.5; SizeZ_mm: 0.6; Value2: 0.1W; VDC_V: 50V; AEC Category: Q200
TP32-TP35 = CMP-0003968-1: Test Point, SMT; Manufacturer: Harwin
U14 = CMP-0097120-1: Op Amp Quad Zero Drift Amplifier R-R I/O ±2.75V/5.5V 14-Pin SOIC T/R; Manufacturer: Texas Instruments; Standoff Height: 0.1mm; SizeZ_mm: 1.75mm; Number Of Channels: 4; Max Dual Supply Voltage: 2.75V; Input Bias Current: 0.00003uA; TaMin_C: -55°C; TaMax_C: +150°C; Input Offset Voltage: 0.00225mV; Min Dual Supply Voltage: 1.25V; Output Current Per Channel: 60mA; Response Time: 2us; Gain Bandwidth: 10MHz; Max Supply Voltage: 5.5V; Voltage Gain: 148dB; AEC Qualified: No; Nominal Supply Current: 1.7-1.9mA; Min Supply Voltage: 2.5V

## Sheet TIDA-010957-DCAC-PWM-BUFFER.SchDoc
size 431 x 279 mm; Date: Not shown in title block; ApprovedBy: Not shown in title block; CheckedBy: Not shown in title block; Author: Not shown in title block; CompanyName: Not shown in title block; Engineer: Not shown in title block; Organization: Not shown in title block; Address1: Not shown in title block; Address2: Not shown in title block; Address3: Not shown in title block; Address4: Not shown in title block; DocumentNumber: 1; Revision: Use project parameter SCH_Rev; SheetNumber: 10; SheetTotal: 12; PageSetup: Record=PageOptions¦CenterHorizontal=True¦CenterVertical=True¦PrintScale=1.00¦XCorrection=1.00¦YCorrection=1.00¦PrintKind=0¦BorderSize=5000000¦LeftOffset=0¦BottomOffset=0¦Orientation=2¦PaperLength=1000¦PaperWidth=1000¦Scale=100¦PaperSource=15¦PrintQuality=600¦MediaType=1¦DitherType=10¦PaperKind=Letter¦PrintScaleMode=1
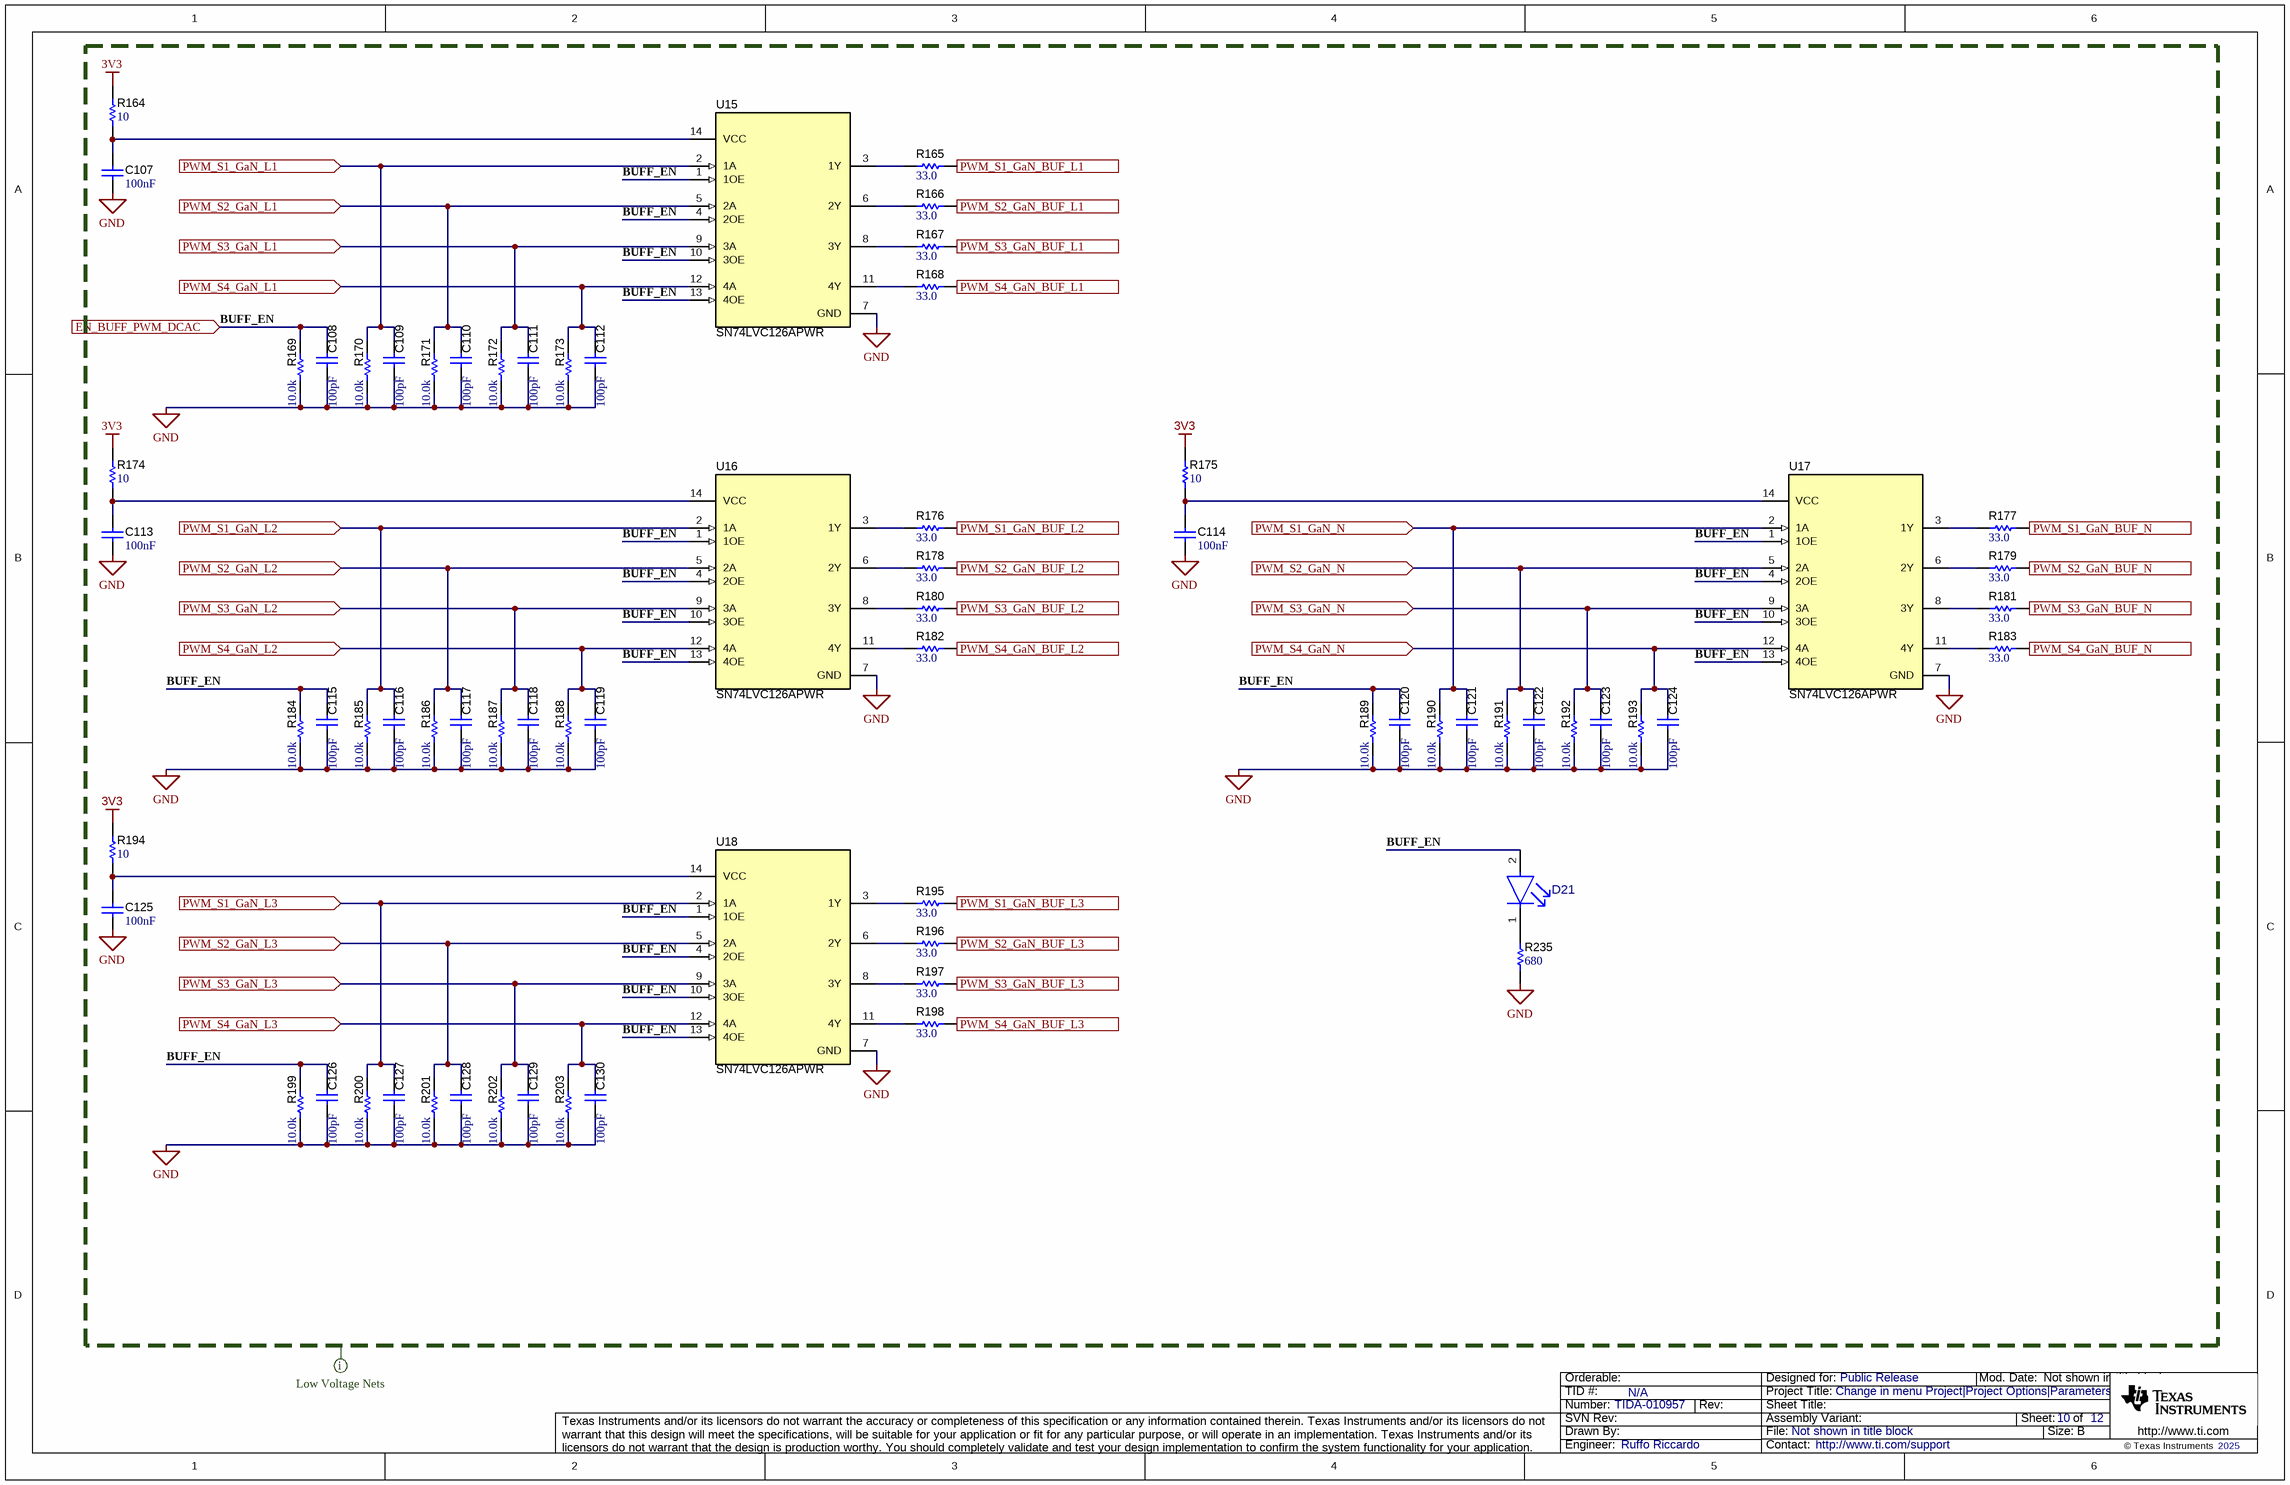
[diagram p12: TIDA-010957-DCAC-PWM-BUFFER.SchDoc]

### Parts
C107  Cap_F: 100nF  [0603]  (hidden comment: 06033C104JAT2A)
C108  ValueDisplayed: 100pF  [0402L]  (hidden comment: GRM1555C1H101JA01D)
C109  ValueDisplayed: 100pF  [0402L]  (hidden comment: GRM1555C1H101JA01D)
C110  ValueDisplayed: 100pF  [0402L]  (hidden comment: GRM1555C1H101JA01D)
C111  ValueDisplayed: 100pF  [0402L]  (hidden comment: GRM1555C1H101JA01D)
C112  ValueDisplayed: 100pF  [0402L]  (hidden comment: GRM1555C1H101JA01D)
C113  Cap_F: 100nF  [0603]  (hidden comment: 06033C104JAT2A)
C114  Cap_F: 100nF  [0603]  (hidden comment: 06033C104JAT2A)
C115  ValueDisplayed: 100pF  [0402L]  (hidden comment: GRM1555C1H101JA01D)
C116  ValueDisplayed: 100pF  [0402L]  (hidden comment: GRM1555C1H101JA01D)
C117  ValueDisplayed: 100pF  [0402L]  (hidden comment: GRM1555C1H101JA01D)
C118  ValueDisplayed: 100pF  [0402L]  (hidden comment: GRM1555C1H101JA01D)
C119  ValueDisplayed: 100pF  [0402L]  (hidden comment: GRM1555C1H101JA01D)
C120  ValueDisplayed: 100pF  [0402L]  (hidden comment: GRM1555C1H101JA01D)
C121  ValueDisplayed: 100pF  [0402L]  (hidden comment: GRM1555C1H101JA01D)
C122  ValueDisplayed: 100pF  [0402L]  (hidden comment: GRM1555C1H101JA01D)
C123  ValueDisplayed: 100pF  [0402L]  (hidden comment: GRM1555C1H101JA01D)
C124  ValueDisplayed: 100pF  [0402L]  (hidden comment: GRM1555C1H101JA01D)
C125  Cap_F: 100nF  [0603]  (hidden comment: 06033C104JAT2A)
C126  ValueDisplayed: 100pF  [0402L]  (hidden comment: GRM1555C1H101JA01D)
C127  ValueDisplayed: 100pF  [0402L]  (hidden comment: GRM1555C1H101JA01D)
C128  ValueDisplayed: 100pF  [0402L]  (hidden comment: GRM1555C1H101JA01D)
C129  ValueDisplayed: 100pF  [0402L]  (hidden comment: GRM1555C1H101JA01D)
C130  ValueDisplayed: 100pF  [0402L]  (hidden comment: GRM1555C1H101JA01D)
D21  KG DELLS1.22-JGKH-24  [FP-KG DELLS1.22-JGKH-24_0603-MFG]  (value not drawn)
R164  ValueDisplayed: 10  [0402L]  (hidden comment: CRCW040210R0JNED)
R165  ValueDisplayed: 33.0  [0402L]  (hidden comment: ERJ-2RKF33R0X)
R166  ValueDisplayed: 33.0  [0402L]  (hidden comment: ERJ-2RKF33R0X)
R167  ValueDisplayed: 33.0  [0402L]  (hidden comment: ERJ-2RKF33R0X)
R168  ValueDisplayed: 33.0  [0402L]  (hidden comment: ERJ-2RKF33R0X)
R169  ValueDisplayed: 10.0k  [0402L]  (hidden comment: CRCW040210K0FKED)
R170  ValueDisplayed: 10.0k  [0402L]  (hidden comment: CRCW040210K0FKED)
R171  ValueDisplayed: 10.0k  [0402L]  (hidden comment: CRCW040210K0FKED)
R172  ValueDisplayed: 10.0k  [0402L]  (hidden comment: CRCW040210K0FKED)
R173  ValueDisplayed: 10.0k  [0402L]  (hidden comment: CRCW040210K0FKED)
R174  ValueDisplayed: 10  [0402L]  (hidden comment: CRCW040210R0JNED)
R175  ValueDisplayed: 10  [0402L]  (hidden comment: CRCW040210R0JNED)
R176  ValueDisplayed: 33.0  [0402L]  (hidden comment: ERJ-2RKF33R0X)
R177  ValueDisplayed: 33.0  [0402L]  (hidden comment: ERJ-2RKF33R0X)
R178  ValueDisplayed: 33.0  [0402L]  (hidden comment: ERJ-2RKF33R0X)
R179  ValueDisplayed: 33.0  [0402L]  (hidden comment: ERJ-2RKF33R0X)
R180  ValueDisplayed: 33.0  [0402L]  (hidden comment: ERJ-2RKF33R0X)
R181  ValueDisplayed: 33.0  [0402L]  (hidden comment: ERJ-2RKF33R0X)
R182  ValueDisplayed: 33.0  [0402L]  (hidden comment: ERJ-2RKF33R0X)
R183  ValueDisplayed: 33.0  [0402L]  (hidden comment: ERJ-2RKF33R0X)
R184  ValueDisplayed: 10.0k  [0402L]  (hidden comment: CRCW040210K0FKED)
R185  ValueDisplayed: 10.0k  [0402L]  (hidden comment: CRCW040210K0FKED)
R186  ValueDisplayed: 10.0k  [0402L]  (hidden comment: CRCW040210K0FKED)
R187  ValueDisplayed: 10.0k  [0402L]  (hidden comment: CRCW040210K0FKED)
R188  ValueDisplayed: 10.0k  [0402L]  (hidden comment: CRCW040210K0FKED)
R189  ValueDisplayed: 10.0k  [0402L]  (hidden comment: CRCW040210K0FKED)
R190  ValueDisplayed: 10.0k  [0402L]  (hidden comment: CRCW040210K0FKED)
R191  ValueDisplayed: 10.0k  [0402L]  (hidden comment: CRCW040210K0FKED)
R192  ValueDisplayed: 10.0k  [0402L]  (hidden comment: CRCW040210K0FKED)
R193  ValueDisplayed: 10.0k  [0402L]  (hidden comment: CRCW040210K0FKED)
R194  ValueDisplayed: 10  [0402L]  (hidden comment: CRCW040210R0JNED)
R195  ValueDisplayed: 33.0  [0402L]  (hidden comment: ERJ-2RKF33R0X)
R196  ValueDisplayed: 33.0  [0402L]  (hidden comment: ERJ-2RKF33R0X)
R197  ValueDisplayed: 33.0  [0402L]  (hidden comment: ERJ-2RKF33R0X)
R198  ValueDisplayed: 33.0  [0402L]  (hidden comment: ERJ-2RKF33R0X)
R199  ValueDisplayed: 10.0k  [0402L]  (hidden comment: CRCW040210K0FKED)
R200  ValueDisplayed: 10.0k  [0402L]  (hidden comment: CRCW040210K0FKED)
R201  ValueDisplayed: 10.0k  [0402L]  (hidden comment: CRCW040210K0FKED)
R202  ValueDisplayed: 10.0k  [0402L]  (hidden comment: CRCW040210K0FKED)
R203  ValueDisplayed: 10.0k  [0402L]  (hidden comment: CRCW040210K0FKED)
R235  ValueDisplayed: 680  [0603]  (hidden comment: RC0603JR-07680RL)
U15  SN74LVC126APWR  [PW0014A_N]
U16  SN74LVC126APWR  [PW0014A_N]
U17  SN74LVC126APWR  [PW0014A_N]
U18  SN74LVC126APWR  [PW0014A_N]

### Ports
EN_BUFF_PWM_DCAC (in), PWM_S1_GaN_BUF_L1 (out), PWM_S1_GaN_BUF_L2 (out), PWM_S1_GaN_BUF_L3 (out), PWM_S1_GaN_BUF_N (out), PWM_S1_GaN_L1 (in), PWM_S1_GaN_L2 (in), PWM_S1_GaN_L3 (in), PWM_S1_GaN_N (in), PWM_S2_GaN_BUF_L1 (out), PWM_S2_GaN_BUF_L2 (out), PWM_S2_GaN_BUF_L3 (out), PWM_S2_GaN_BUF_N (out), PWM_S2_GaN_L1 (in), PWM_S2_GaN_L2 (in), PWM_S2_GaN_L3 (in), PWM_S2_GaN_N (in), PWM_S3_GaN_BUF_L1 (out), PWM_S3_GaN_BUF_L2 (out), PWM_S3_GaN_BUF_L3 (out), PWM_S3_GaN_BUF_N (out), PWM_S3_GaN_L1 (in), PWM_S3_GaN_L2 (in), PWM_S3_GaN_L3 (in), PWM_S3_GaN_N (in), PWM_S4_GaN_BUF_L1 (out), PWM_S4_GaN_BUF_L2 (out), PWM_S4_GaN_BUF_L3 (out), PWM_S4_GaN_BUF_N (out), PWM_S4_GaN_L1 (in), PWM_S4_GaN_L2 (in), PWM_S4_GaN_L3 (in), PWM_S4_GaN_N (in)

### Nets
3V3: R164.2 R174.2 R175.2 R194.2
GND: C107.2 C108.2 C109.2 C110.2 C111.2 C112.2 C113.2 C114.2 C115.2 C116.2 C117.2 C118.2 C119.2 C120.2 C121.2 C122.2 C123.2 C124.2 C125.2 C126.2 C127.2 C128.2 C129.2 C130.2 R169.1 R170.1 R171.1 R172.1 R173.1 R184.1 R185.1 R186.1 R187.1 R188.1 R189.1 R190.1 R191.1 R192.1 R193.1 R199.1 R200.1 R201.1 R202.1 R203.1 R235.1 U15.7(GND) U16.7(GND) U17.7(GND) U18.7(GND)
BUFF_EN: C108.1 C115.1 C120.1 C126.1 D21.2(ANODE) R169.2 R184.2 R189.2 R199.2 U15.1(1OE) U15.4(2OE) U15.10(3OE) U15.13(4OE) U16.1(1OE) U16.4(2OE) U16.10(3OE) U16.13(4OE) U17.1(1OE) U17.4(2OE) U17.10(3OE) U17.13(4OE) U18.1(1OE) U18.4(2OE) U18.10(3OE) U18.13(4OE) ; port EN_BUFF_PWM_DCAC
PWM_S1_GaN_BUF_L1: R165.2 ; port PWM_S1_GaN_BUF_L1
PWM_S1_GaN_BUF_L2: R176.2 ; port PWM_S1_GaN_BUF_L2
PWM_S1_GaN_BUF_L3: R195.2 ; port PWM_S1_GaN_BUF_L3
PWM_S1_GaN_BUF_N: R177.2 ; port PWM_S1_GaN_BUF_N
PWM_S1_GaN_L1: C109.1 R170.2 U15.2(1A) ; port PWM_S1_GaN_L1
PWM_S1_GaN_L2: C116.1 R185.2 U16.2(1A) ; port PWM_S1_GaN_L2
PWM_S1_GaN_L3: C127.1 R200.2 U18.2(1A) ; port PWM_S1_GaN_L3
PWM_S1_GaN_N: C121.1 R190.2 U17.2(1A) ; port PWM_S1_GaN_N
PWM_S2_GaN_BUF_L1: R166.2 ; port PWM_S2_GaN_BUF_L1
PWM_S2_GaN_BUF_L2: R178.2 ; port PWM_S2_GaN_BUF_L2
PWM_S2_GaN_BUF_L3: R196.2 ; port PWM_S2_GaN_BUF_L3
PWM_S2_GaN_BUF_N: R179.2 ; port PWM_S2_GaN_BUF_N
PWM_S2_GaN_L1: C110.1 R171.2 U15.5(2A) ; port PWM_S2_GaN_L1
PWM_S2_GaN_L2: C117.1 R186.2 U16.5(2A) ; port PWM_S2_GaN_L2
PWM_S2_GaN_L3: C128.1 R201.2 U18.5(2A) ; port PWM_S2_GaN_L3
PWM_S2_GaN_N: C122.1 R191.2 U17.5(2A) ; port PWM_S2_GaN_N
PWM_S3_GaN_BUF_L1: R167.2 ; port PWM_S3_GaN_BUF_L1
PWM_S3_GaN_BUF_L2: R180.2 ; port PWM_S3_GaN_BUF_L2
PWM_S3_GaN_BUF_L3: R197.2 ; port PWM_S3_GaN_BUF_L3
PWM_S3_GaN_BUF_N: R181.2 ; port PWM_S3_GaN_BUF_N
PWM_S3_GaN_L1: C111.1 R172.2 U15.9(3A) ; port PWM_S3_GaN_L1
PWM_S3_GaN_L2: C118.1 R187.2 U16.9(3A) ; port PWM_S3_GaN_L2
PWM_S3_GaN_L3: C129.1 R202.2 U18.9(3A) ; port PWM_S3_GaN_L3
PWM_S3_GaN_N: C123.1 R192.2 U17.9(3A) ; port PWM_S3_GaN_N
PWM_S4_GaN_BUF_L1: R168.2 ; port PWM_S4_GaN_BUF_L1
PWM_S4_GaN_BUF_L2: R182.2 ; port PWM_S4_GaN_BUF_L2
PWM_S4_GaN_BUF_L3: R198.2 ; port PWM_S4_GaN_BUF_L3
PWM_S4_GaN_BUF_N: R183.2 ; port PWM_S4_GaN_BUF_N
PWM_S4_GaN_L1: C112.1 R173.2 U15.12(4A) ; port PWM_S4_GaN_L1
PWM_S4_GaN_L2: C119.1 R188.2 U16.12(4A) ; port PWM_S4_GaN_L2
PWM_S4_GaN_L3: C130.1 R203.2 U18.12(4A) ; port PWM_S4_GaN_L3
PWM_S4_GaN_N: C124.1 R193.2 U17.12(4A) ; port PWM_S4_GaN_N
NetC107_1: C107.1 R164.1 U15.14(VCC)
NetC113_1: C113.1 R174.1 U16.14(VCC)
NetC114_1: C114.1 R175.1 U17.14(VCC)
NetC125_1: C125.1 R194.1 U18.14(VCC)
NetD21_1: D21.1(CATHODE) R235.2
NetR165_1: R165.1 U15.3(1Y)
NetR166_1: R166.1 U15.6(2Y)
NetR167_1: R167.1 U15.8(3Y)
NetR168_1: R168.1 U15.11(4Y)
NetR176_1: R176.1 U16.3(1Y)
NetR177_1: R177.1 U17.3(1Y)
NetR178_1: R178.1 U16.6(2Y)
NetR179_1: R179.1 U17.6(2Y)
NetR180_1: R180.1 U16.8(3Y)
NetR181_1: R181.1 U17.8(3Y)
NetR182_1: R182.1 U16.11(4Y)
NetR183_1: R183.1 U17.11(4Y)
NetR195_1: R195.1 U18.3(1Y)
NetR196_1: R196.1 U18.6(2Y)
NetR197_1: R197.1 U18.8(3Y)
NetR198_1: R198.1 U18.11(4Y)

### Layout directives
net class LV_NET: 3V3, BUFF_EN, GND

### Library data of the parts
C107 C113 C114 C125 = CMP-0006752-5: as C30 on sheet TIDA-010957-DCAC-Current-Sensing
C108-C112 C115-C124 C126-C130 = CMP-0006410-2: CAP, CERM, 100 pF, 50 V, +/- 5%, C0G/NP0, 0402; Manufacturer: MuRata; TaMin_C: -55°C; Polarized: N; SizeAreaWB_mm2: 3; Value1: Unknown; U/M: EA; Value: 100pF; TaMax_C: 125°C; SizeZ_mm: 0.6; SizeX_mm: 1; SizeY_mm: 0.5; Cap_Case: 0402; Value2: 50V; AEC Category: Q200
D21 = CMP-0093310-1: Standard LEDs - SMD Green TOPLED E 1608; Manufacturer: Osram Opto; AEC Grade: Grade 2; LambdaP: 572nm; SizeZ_mm: 0.7mm; LuminousFlux_PhiV: 0.016-0.0295lm; Luminous Intensity: 4.5-9.7mcd; LambdaD: 570nm; Tjmax_C: 125°C; Angle: 120°; Led Orientation: Top View; Forward Current: 2mA; Vf_V: 1.8V; AEC Qualified: Yes; Vr_V: 12V
R164 R174 R175 R194 = CMP-0026827-3: as R332 on sheet TIDA-010957-DCAC-DC-Voltage-Measurements
R165-R168 R176-R183 R195-R198 = CMP-0026696-1: as R146 on sheet TIDA-010957-DCAC-FC-OP-AMP
R169-R173 R184-R193 R199-R203 = CMP-0025958-3: RES, 10.0 k, 1%, 0.063 W, AEC-Q200 Grade 0, 0402; Manufacturer: Vishay-Dale; Power_W: 63mW; TempCo: 100 ppm/C; Value_Code: 10k0; Value: 10.0k; EIA_Code: E96; Res_ohm: 10k; SizeX_mm: 1; SizeY_mm: 0.5; SizeZ_mm: 0.6; Value2: 0.063W; AEC Qualified: Y; VDC_V: 50V; AEC Category: Q200; AEC Grade: 0
R235 = CMP-0025936-5: RES, 680, 5%, 0.1 W, 0603; Manufacturer: Yageo; Power_W: 100mW; TempCo: 100 ppm/C; Value_Code: 680R; Value: 680; EIA_Code: E24; SizeX_mm: 1.6; SizeY_mm: 0.8; SizeZ_mm: 1; Value2: 0.1W; SizeArea_mm2: 1.28; AEC Qualified: N; VDC_V: 75V; AEC Category: Q200; SizeAreaWB_mm2: 4.68
U15-U18 = CMP-0066280-1: Quadruple Bus Buffer Gate with 3-State Outputs, PW0014A (TSSOP-14); Manufacturer: Texas Instruments; SizeArea_mm2: 32.0; SizeAreaWB_mm2: 58.8; SizeX_mm: 6.4; SizeY_mm: 5.0; SizeZ_mm: 1.2; CompType: IC; U/M: EA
